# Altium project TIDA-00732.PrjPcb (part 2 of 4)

## Sheet TIDA-00732_ADC.SchDoc: Analog Front End & ADC
size 431 x 279 mm; Date: Not shown in title block; ApprovedBy: Not shown in title block; CheckedBy: Not shown in title block; Author: Not shown in title block; CompanyName: Not shown in title block; DrawnBy: Anbu Mani; Engineer: Not shown in title block; Organization: Not shown in title block; Address1: Not shown in title block; Address2: Not shown in title block; Address3: Not shown in title block; Address4: Not shown in title block; DocumentNumber: 1; Revision: Use project parameter SCH_Rev; SheetNumber: 4; SheetTotal: 10; PageSetup: Record=PageOptions¦CenterHorizontal=True¦CenterVertical=True¦PrintScale=1.00¦XCorrection=1.00¦YCorrection=1.00¦PrintKind=0¦BorderSize=5000000¦LeftOffset=0¦BottomOffset=0¦Orientation=2¦PaperLength=1000¦PaperWidth=1000¦Scale=100¦PaperSource=15¦PrintQuality=600¦MediaType=1¦DitherType=10¦PaperKind=Letter¦PrintScaleMode=1
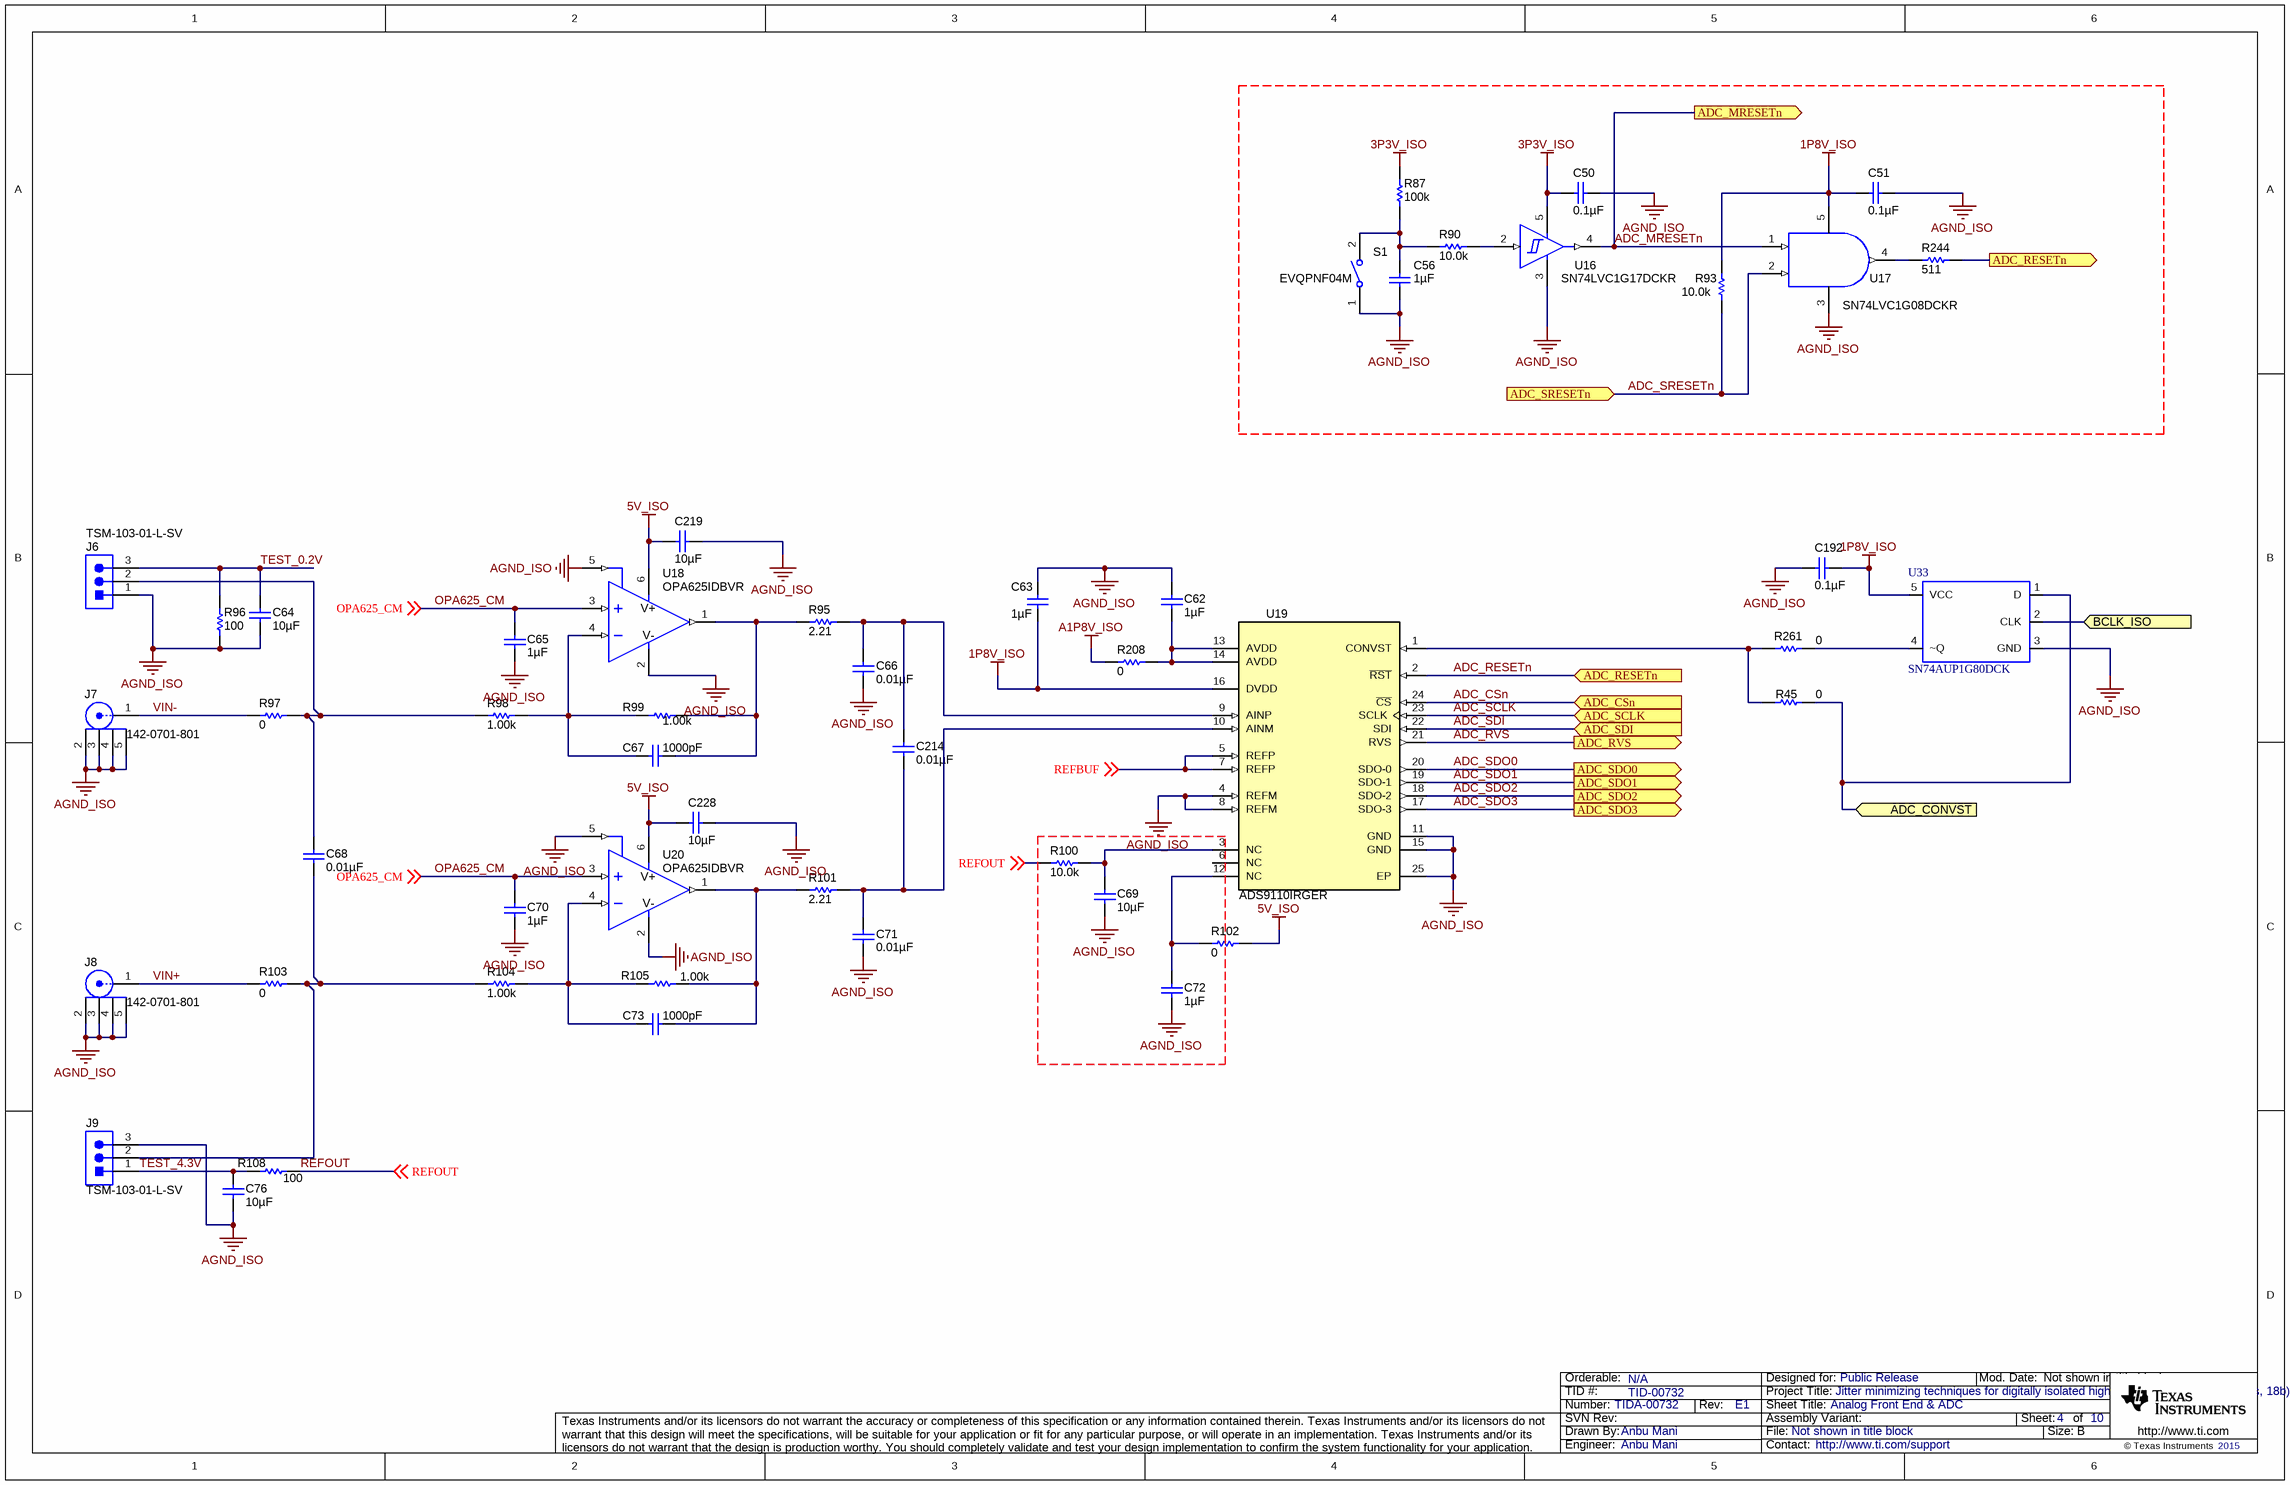
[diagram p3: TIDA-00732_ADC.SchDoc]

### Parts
C50  ValueDisplayed: 0.1µF  [0603]  (hidden comment: 0603YC104JAT2A)
C51  ValueDisplayed: 0.1µF  [0402]  (hidden comment: GRM155R71C104KA88D)
C56  ValueDisplayed: 1µF  [0603]  (hidden comment: GRM188R71E105KA12D)
C62  ValueDisplayed: 1µF  [0603]  (hidden comment: GRM188R71E105KA12D)
C63  ValueDisplayed: 1µF  [0603]  (hidden comment: GRM188R71E105KA12D)
C64  ValueDisplayed: 10µF  [0805_HV]  (hidden comment: GRM21BR71A106KE51L)
C65  ValueDisplayed: 1µF  [0603]  (hidden comment: GRM188R71E105KA12D)
C66  ValueDisplayed: 0.01µF  [0402]  (hidden comment: GRM155R71H103KA88D)
C67  ValueDisplayed: 1000pF  [0603]  (hidden comment: GRM1885C1H102FA01J)
C68  ValueDisplayed: 0.01µF  [0805_HV]  (hidden comment: C0805C103F1GACTU)
C69  ValueDisplayed: 10µF  [0805_HV]  (hidden comment: GRM21BR71A106KE51L)
C70  ValueDisplayed: 1µF  [0603]  (hidden comment: GRM188R71E105KA12D)
C71  ValueDisplayed: 0.01µF  [0402]  (hidden comment: GRM155R71H103KA88D)
C72  ValueDisplayed: 1µF  [0603]  (hidden comment: GRM188R71E105KA12D)
C73  ValueDisplayed: 1000pF  [0603]  (hidden comment: GRM1885C1H102FA01J)
C76  ValueDisplayed: 10µF  [0805_HV]  (hidden comment: GRM21BR71A106KE51L)
C192  ValueDisplayed: 0.1µF  [0402]  (hidden comment: GRM155R71C104KA88D)
C214  ValueDisplayed: 0.01µF  [0402]  (hidden comment: GRM155R71H103KA88D)
C219  ValueDisplayed: 10µF  [0603_120]  (hidden comment: ZRB18AD71A106KE01L)
C228  ValueDisplayed: 10µF  [0603_120]  (hidden comment: ZRB18AD71A106KE01L)
J6  TSM-103-01-L-SV  [Samtec_TSM-103-01-X-SV]
J7  142-0701-801  [JOHNSON_142-0701-801]
J8  142-0701-801  [JOHNSON_142-0701-801]
J9  TSM-103-01-L-SV  [Samtec_TSM-103-01-X-SV]
R45  ValueDisplayed: 0  [0402]  (hidden comment: CRCW04020000Z0ED)
R87  ValueDisplayed: 100k  [0402]  (hidden comment: CRCW0402100KFKED)
R90  ValueDisplayed: 10.0k  [0402]  (hidden comment: ERJ-2RKF1002X)
R93  ValueDisplayed: 10.0k  [0402]  (hidden comment: ERJ-2RKF1002X)
R95  ValueDisplayed: 2.21  [0603]  (hidden comment: CRCW06032R21FKEA)
R96  ValueDisplayed: 100  [0603]  (hidden comment: RG1608P-101-B-T5)
R97  ValueDisplayed: 0  [0603]  (hidden comment: ERJ-3GEY0R00V)
R98  ValueDisplayed: 1.00k  [0603]  (hidden comment: RG1608P-102-B-T5)
R99  ValueDisplayed: 1.00k  [0603]  (hidden comment: RG1608P-102-B-T5)
R100  ValueDisplayed: 10.0k  [0402]  (hidden comment: ERJ-2RKF1002X)
R101  ValueDisplayed: 2.21  [0603]  (hidden comment: CRCW06032R21FKEA)
R102  ValueDisplayed: 0  [0402]  (hidden comment: ERJ-2GE0R00X)
R103  ValueDisplayed: 0  [0603]  (hidden comment: ERJ-3GEY0R00V)
R104  ValueDisplayed: 1.00k  [0603]  (hidden comment: RG1608P-102-B-T5)
R105  ValueDisplayed: 1.00k  [0603]  (hidden comment: RG1608P-102-B-T5)
R108  ValueDisplayed: 100  [0603]  (hidden comment: RG1608P-101-B-T5)
R208  ValueDisplayed: 0  [0402]  (hidden comment: ERJ-2GE0R00X)
R244  ValueDisplayed: 511  [0603]  (hidden comment: RC0603FR-07511RL)
R261  ValueDisplayed: 0  [0402]  (hidden comment: CRCW04020000Z0ED)
S1  EVQPNF04M  [SW_EVQPNF04M]
U16  SN74LVC1G17DCKR  [DCK0005A_N]
U17  SN74LVC1G08DCKR  [DCK0005A_N]
U18  OPA625IDBVR  [DBV0006A_N]
U19  ADS9110IRGER  [RGE0024H]
U20  OPA625IDBVR  [DBV0006A_N]
U33  SN74AUP1G80DCK  [DCK-5]

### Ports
ADC_CONVST (in), ADC_CSn (in), ADC_MRESETn (out), ADC_RESETn (in), ADC_RESETn (out), ADC_RVS (out), ADC_SCLK (in), ADC_SDI (in), ADC_SDO0 (out), ADC_SDO1 (out), ADC_SDO2 (out), ADC_SDO3 (out), ADC_SRESETn (in), BCLK_ISO (in)

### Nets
1P8V_ISO: C51.2 C63.2 C192.2 R93.2 U17.5(V+) U19.16(DVDD) U33.5(VCC)
3P3V_ISO: C50.2 R87.2 U16.5(VCC)
5V_ISO: C219.2 C228.2 R102.2 U18.6(V+) U20.6(V+)
A1P8V_ISO: R208.1
AGND_ISO: C50.1 C51.1 C56.2 C62.2 C63.1 C64.2 C65.2 C66.2 C69.2 C70.2 C71.2 C72.2 C76.2 C192.1 C219.1 C228.1 J6.1 J7.2 J7.3 J7.4 J7.5 J8.2 J8.3 J8.4 J8.5 J9.3 R96.1 S1.1 U16.3(GND) U17.3(V-) U18.2(V-) U18.5(MODE) U19.4(REFM) U19.8(REFM) U19.11(GND) U19.15(GND) U19.25(EP) U20.2(V-) U20.5(MODE) U33.3(GND)
ADC_CONVST: R45.2 U33.1(D) ; port ADC_CONVST
ADC_CSn: U19.24(~{CS}) ; port ADC_CSn
ADC_MRESETn: U16.4(Y) U17.1(A) ; port ADC_MRESETn
ADC_RESETn: R244.2 U19.2(~{RST}) ; port ADC_RESETn
ADC_RVS: U19.21(RVS) ; port ADC_RVS
ADC_SCLK: U19.23(SCLK) ; port ADC_SCLK
ADC_SDI: U19.22(SDI) ; port ADC_SDI
ADC_SDO0: U19.20(SDO-0) ; port ADC_SDO0
ADC_SDO1: U19.19(SDO-1) ; port ADC_SDO1
ADC_SDO2: U19.18(SDO-2) ; port ADC_SDO2
ADC_SDO3: U19.17(SDO-3) ; port ADC_SDO3
ADC_SRESETn: R93.1 U17.2(B) ; port ADC_SRESETn
BCLK_ISO: U33.2(CLK) ; port BCLK_ISO
OPA625_CM: C65.1 C70.1 U18.3(IN+) U20.3(IN+) ; off-sheet OPA625_CM
REFBUF: U19.5(REFP) U19.7(REFP) ; off-sheet REFBUF
REFOUT: R100.1 R108.2 ; off-sheet REFOUT
TEST_0.2V: C64.1 J6.3 R96.2
TEST_4.3V: C76.1 J9.1 R108.1
VIN+: J8.1 R103.1
VIN-: J7.1 R97.1
NetC56_1: C56.1 R87.1 R90.1 S1.2
NetC62_1: C62.1 R208.2 U19.13(AVDD) U19.14(AVDD)
NetC66_1: C66.1 C214.1 R95.2 U19.9(AINP)
NetC67_1: C67.1 R95.1 R99.2 U18.1(OUT)
NetC67_2: C67.2 R98.2 R99.1 U18.4(IN-)
NetC68_1: C68.1 J9.2 R103.2 R104.1
NetC68_2: C68.2 J6.2 R97.2 R98.1
NetC69_1: C69.1 R100.2 U19.3(NC)
NetC71_1: C71.1 C214.2 R101.2 U19.10(AINM)
NetC72_1: C72.1 R102.1 U19.12(NC)
NetC73_1: C73.1 R101.1 R105.2 U20.1(OUT)
NetC73_2: C73.2 R104.2 R105.1 U20.4(IN-)
NetR45_1: R45.1 R261.1 U19.1(CONVST)
NetR90_2: R90.2 U16.2(A)
NetR244_1: R244.1 U17.4(Y)
NetR261_2: R261.2 U33.4(~Q)

Not connected (* = marked no-connect by the designer): U19 6(NC)

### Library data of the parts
C50 = 0603YC104JAT2A: CAP, CERM, 0.1 µF, 16 V, +/- 5%, X7R, 0603; Manufacturer: AVX; Polarized: N; CompType: Capacitor; Value: 0.1uF; U/M: EA; Cap_F: 0.0000001; Tolerance_%: 5; ESR_ohm: 0.039; Value1: 0.039 ohm; VDC_V: 16; Value2: 16V; TaMin_C: -55; TaMax_C: 125
C51 C192 = GRM155R71C104KA88D: CAP, CERM, 0.1 µF, 16 V, +/- 10%, X7R, 0402; Manufacturer: MuRata; Polarized: N; CompType: Capacitor; Value: 0.1uF; U/M: EA; Cap_F: 0.0000001; Tolerance_%: 10; Value1: Unknown; VDC_V: 16; Value2: 16V; TaMin_C: -55; TaMax_C: 125
C56 C62 C63 C65 C70 = GRM188R71E105KA12D: CAP, CERM, 1 µF, 25 V, +/- 10%, X7R, 0603; Manufacturer: MuRata; Polarized: N; CompType: Capacitor; Value: 1uF; U/M: EA; Cap_F: 0.000001; Tolerance_%: 10; Value1: Unknown; VDC_V: 25; Value2: 25V; TaMin_C: -55; TaMax_C: 125
C64 C69 C76 = GRM21BR71A106KE51L: CAP, CERM, 10 µF, 10 V, +/- 10%, X7R, 0805; Manufacturer: MuRata; Polarized: N; CompType: Capacitor; Value: 10uF; U/M: EA; Cap_F: 0.00001; Tolerance_%: 10; ESR_ohm: 0.003; Value1: 0.003 ohm; Value2: 10V; TaMin_C: -55; TaMax_C: 125; Cap_Case: 0805; AEC Category: Q200
C66 C71 C214 = GRM155R71H103KA88D: CAP, CERM, 0.01 µF, 50 V, +/- 10%, X7R, 0402; Manufacturer: MuRata; Polarized: N; CompType: Capacitor; Value: 0.01uF; U/M: EA; Cap_F: 0.00000001; Tolerance_%: 10; Value1: Unknown; VDC_V: 50; Value2: 50V; TaMin_C: -55; TaMax_C: 125
C67 C73 = GRM1885C1H102FA01J: CAP, CERM, 1000 pF, 50 V, +/- 1%, C0G/NP0, 0603; Manufacturer: MuRata; Polarized: N; CompType: Capacitor; Value: 1000pF; U/M: EA; Cap_F: 0.000000001; Tolerance_%: 1; Value1: Unknown; VDC_V: 50; Value2: 50V; TaMin_C: -55; TaMax_C: 125
C68 = C0805C103F1GACTU: CAP, CERM, 0.01 µF, 100 V, +/- 1%, C0G/NP0, 0805; Manufacturer: Kemet; Polarized: N; CompType: Capacitor; Value: 0.01uF; U/M: EA; Cap_F: 0.00000001; Tolerance_%: 1; Value1: Unknown; VDC_V: 100; Value2: 100V; TaMin_C: -55; TaMax_C: 125; Cap_Case: 0805; AEC Category: Q200
C72 = GRM188R71E105KA12D: CAP, CERM, 1 µF, 25 V, +/- 10%, X7R, 0603; Manufacturer: MuRata; Polarized: N; CompType: Capacitor; Value: 1uF; U/M: EA; Cap_F: 0.000001; Tolerance_%: 10; Value1: Unknown; VDC_V: 25; Value2: 25V; TaMin_C: -55; TaMax_C: 125; AEC Category: Q200
C219 C228 = ZRB18AD71A106KE01L: CAP, CERM, 10 µF, 10 V, +/- 10%, X7T, 0603; Manufacturer: MuRata; Polarized: N; CompType: Capacitor; Value: 10uF; U/M: EA; Cap_F: 0.00001; Tolerance_%: 10; Value1: Unknown; Value2: 10V; TaMin_C: -55; TaMax_C: 125; Cap_Case: 0603; AEC Category: Q200
J6 J9 = TSM-103-01-L-SV: Header, 100mil, 3x1, Gold, SMT; Manufacturer: Samtec; SymbolCreator: a0799628; U/M: EA
J7 J8 = 142-0701-801: Connector, End launch SMA, 50 ohm, SMT; Manufacturer: Johnson; SymbolCreator: X0208326; U/M: EA
R45 R261 = CRCW04020000Z0ED: RES, 0, 5%, 0.063 W, 0402; Manufacturer: Vishay-Dale; CompType: Resistor; Value: 0; Value_Code: 0000; Tolerance_%: 5; Power_W: 0.063; Value2: 0.063W; VDC_V: 50; TempCo: 200 ppm/C; EIA_Code: E24; U/M: EA; AEC Category: Q200
R87 = CRCW0402100KFKED: RES, 100 k, 1%, 0.063 W, 0402; Manufacturer: Vishay-Dale; CompType: Resistor; Value: 100k; Res_ohm: 100000; Tolerance_%: 1; Power_W: 0.063; Value2: 0.063W; VDC_V: 50; TempCo: 100 ppm/C; EIA_Code: E96; U/M: EA
R90 R93 = ERJ-2RKF1002X: RES, 10.0 k, 1%, 0.1 W, 0402; Manufacturer: Panasonic; CompType: Resistor; Value: 10.0k; Res_ohm: 10000; Value_Code: 10k0; Tolerance_%: 1; Power_W: 0.1; Value2: 0.1W; VDC_V: 50; TempCo: 100 ppm/C; EIA_Code: E96; U/M: EA
R95 R101 = CRCW06032R21FKEA: RES, 2.21, 1%, 0.1 W, 0603; Manufacturer: Vishay-Dale; CompType: Resistor; Value: 2.21; Value_Code: 2R21; Tolerance_%: 1; Power_W: 0.1; Value2: 0.1W; VDC_V: 75; TempCo: 100 ppm/C; EIA_Code: E96; U/M: EA
R96 R108 = RG1608P-101-B-T5: RES, 100, 0.1%, 0.1 W, 0603; Manufacturer: Susumu Co Ltd; CompType: Resistor; Value: 100; Value_Code: 100R; Tolerance_%: 0.1; Value2: 0.1W; VDC_V: 75; TempCo: 25 ppm/C; EIA_Code: E192; U/M: EA; AEC Category: Q200
R97 R103 = ERJ-3GEY0R00V: RES, 0, 5%, 0.1 W, 0603; Manufacturer: Panasonic; CompType: Resistor; Value: 0; Value_Code: 0000; Tolerance_%: 5; Power_W: 0.1; Value2: 0.1W; VDC_V: 50; TempCo: 600 ppm/C; EIA_Code: E24; U/M: EA; AEC Category: Q200
R98 R99 R104 R105 = RG1608P-102-B-T5: RES, 1.00 k, 0.1%, 0.1 W, 0603; Manufacturer: Susumu Co Ltd; CompType: Resistor; Value: 1.00k; Res_ohm: 1000; Value_Code: 1k00; Tolerance_%: 0.1; Value2: 0.1W; VDC_V: 75; TempCo: 25 ppm/C; EIA_Code: E192; U/M: EA
R100 = ERJ-2RKF1002X: RES, 10.0 k, 1%, 0.1 W, 0402; Manufacturer: Panasonic; CompType: Resistor; Value: 10.0k; Res_ohm: 10000; Value_Code: 10k0; Tolerance_%: 1; Power_W: 0.1; Value2: 0.1W; VDC_V: 50; TempCo: 100 ppm/C; EIA_Code: E96; U/M: EA; AEC Category: Q200
R102 R208 = ERJ-2GE0R00X: RES, 0, 5%, 0.063 W, 0402; Manufacturer: Panasonic; CompType: Resistor; Value: 0; Value_Code: 0000; Tolerance_%: 5; Power_W: 0.063; Value2: 0.063W; VDC_V: 50; TempCo: 600 ppm/C; EIA_Code: E24; U/M: EA; AEC Category: Q200
R244 = RC0603FR-07511RL: RES, 511, 1%, 0.1 W, 0603; Manufacturer: Yageo America; CompType: Resistor; Value: 511; Value_Code: 511R; Tolerance_%: 1; Power_W: 0.1; Value2: 0.1W; VDC_V: 150; TempCo: 200 ppm/C; EIA_Code: E96; U/M: EA; AEC Category: Q200
S1 = EVQPNF04M: Switch, Tactile, SPST-NO, 0.05A, 12V, SMD; Manufacturer: Panasonic; SymbolCreator: a0799628; Circuit: SPST; VDC_V: 12; SwitchFunction: Off-Mom; PositionCount: 1; CurrentRating_mA: 50
U16 = SN74LVC1G17DCKR: SINGLE SCHMITT-TRIGGER BUFFER, DCK0005A; Alternate PartNumber: SN74LVC1G17DCKT; Manufacturer: Texas Instruments; SymbolCreator: a0799628; CompType: IC; U/M: EA
U17 = SN74LVC1G08DCKR: Single 2-Input Positive-AND Gate, DCK0005A; Alternate PartNumber: SN74LVC1G08DCKT; Manufacturer: Texas Instruments; CompType: IC; U/M: EA
U18 U20 = OPA625IDBVR: High-Bandwidth, High-Precision, Low THD+N, 16-Bit and 18-Bit Analog-to-Digital Converter (ADC) Drivers, DBV0006A; Alternate PartNumber: OPA625IDBVT; Manufacturer: Texas Instruments; SymbolCreator: Altium; CompType: IC; U/M: EA
U19 = ADS9110IRGER: 18-Bit, 2-MSPS, 20-mW, SAR ADC with Enhanced Serial Interface, RGE0024H; Alternate PartNumber: ADS9110IRGET; Manufacturer: Texas Instruments; SymbolCreator: Altium; CompType: IC; U/M: EA
U33 = SN74AUP1G80DCK: IC, Single Positive-Edge-Triggered D-Type Flip-Flop; Manufacturer: TI; Alternate Manufacturer: None; Area: 23200

## Sheet TIDA-00732_FPGA_1.SchDoc: FPGA 1 - Isolated End
size 431 x 279 mm; Date: Not shown in title block; ApprovedBy: Not shown in title block; CheckedBy: Not shown in title block; Author: Not shown in title block; CompanyName: Not shown in title block; DrawnBy: Anbu Mani; Engineer: Not shown in title block; Organization: Not shown in title block; Address1: Not shown in title block; Address2: Not shown in title block; Address3: Not shown in title block; Address4: Not shown in title block; DocumentNumber: 1; Revision: Use project parameter SCH_Rev; SheetNumber: 5; SheetTotal: 10; PageSetup: Record=PageOptions¦CenterHorizontal=True¦CenterVertical=True¦PrintScale=1.00¦XCorrection=1.00¦YCorrection=1.00¦PrintKind=0¦BorderSize=5000000¦LeftOffset=0¦BottomOffset=0¦Orientation=2¦PaperLength=1000¦PaperWidth=1000¦Scale=100¦PaperSource=15¦PrintQuality=600¦MediaType=1¦DitherType=10¦PaperKind=Letter¦PrintScaleMode=1
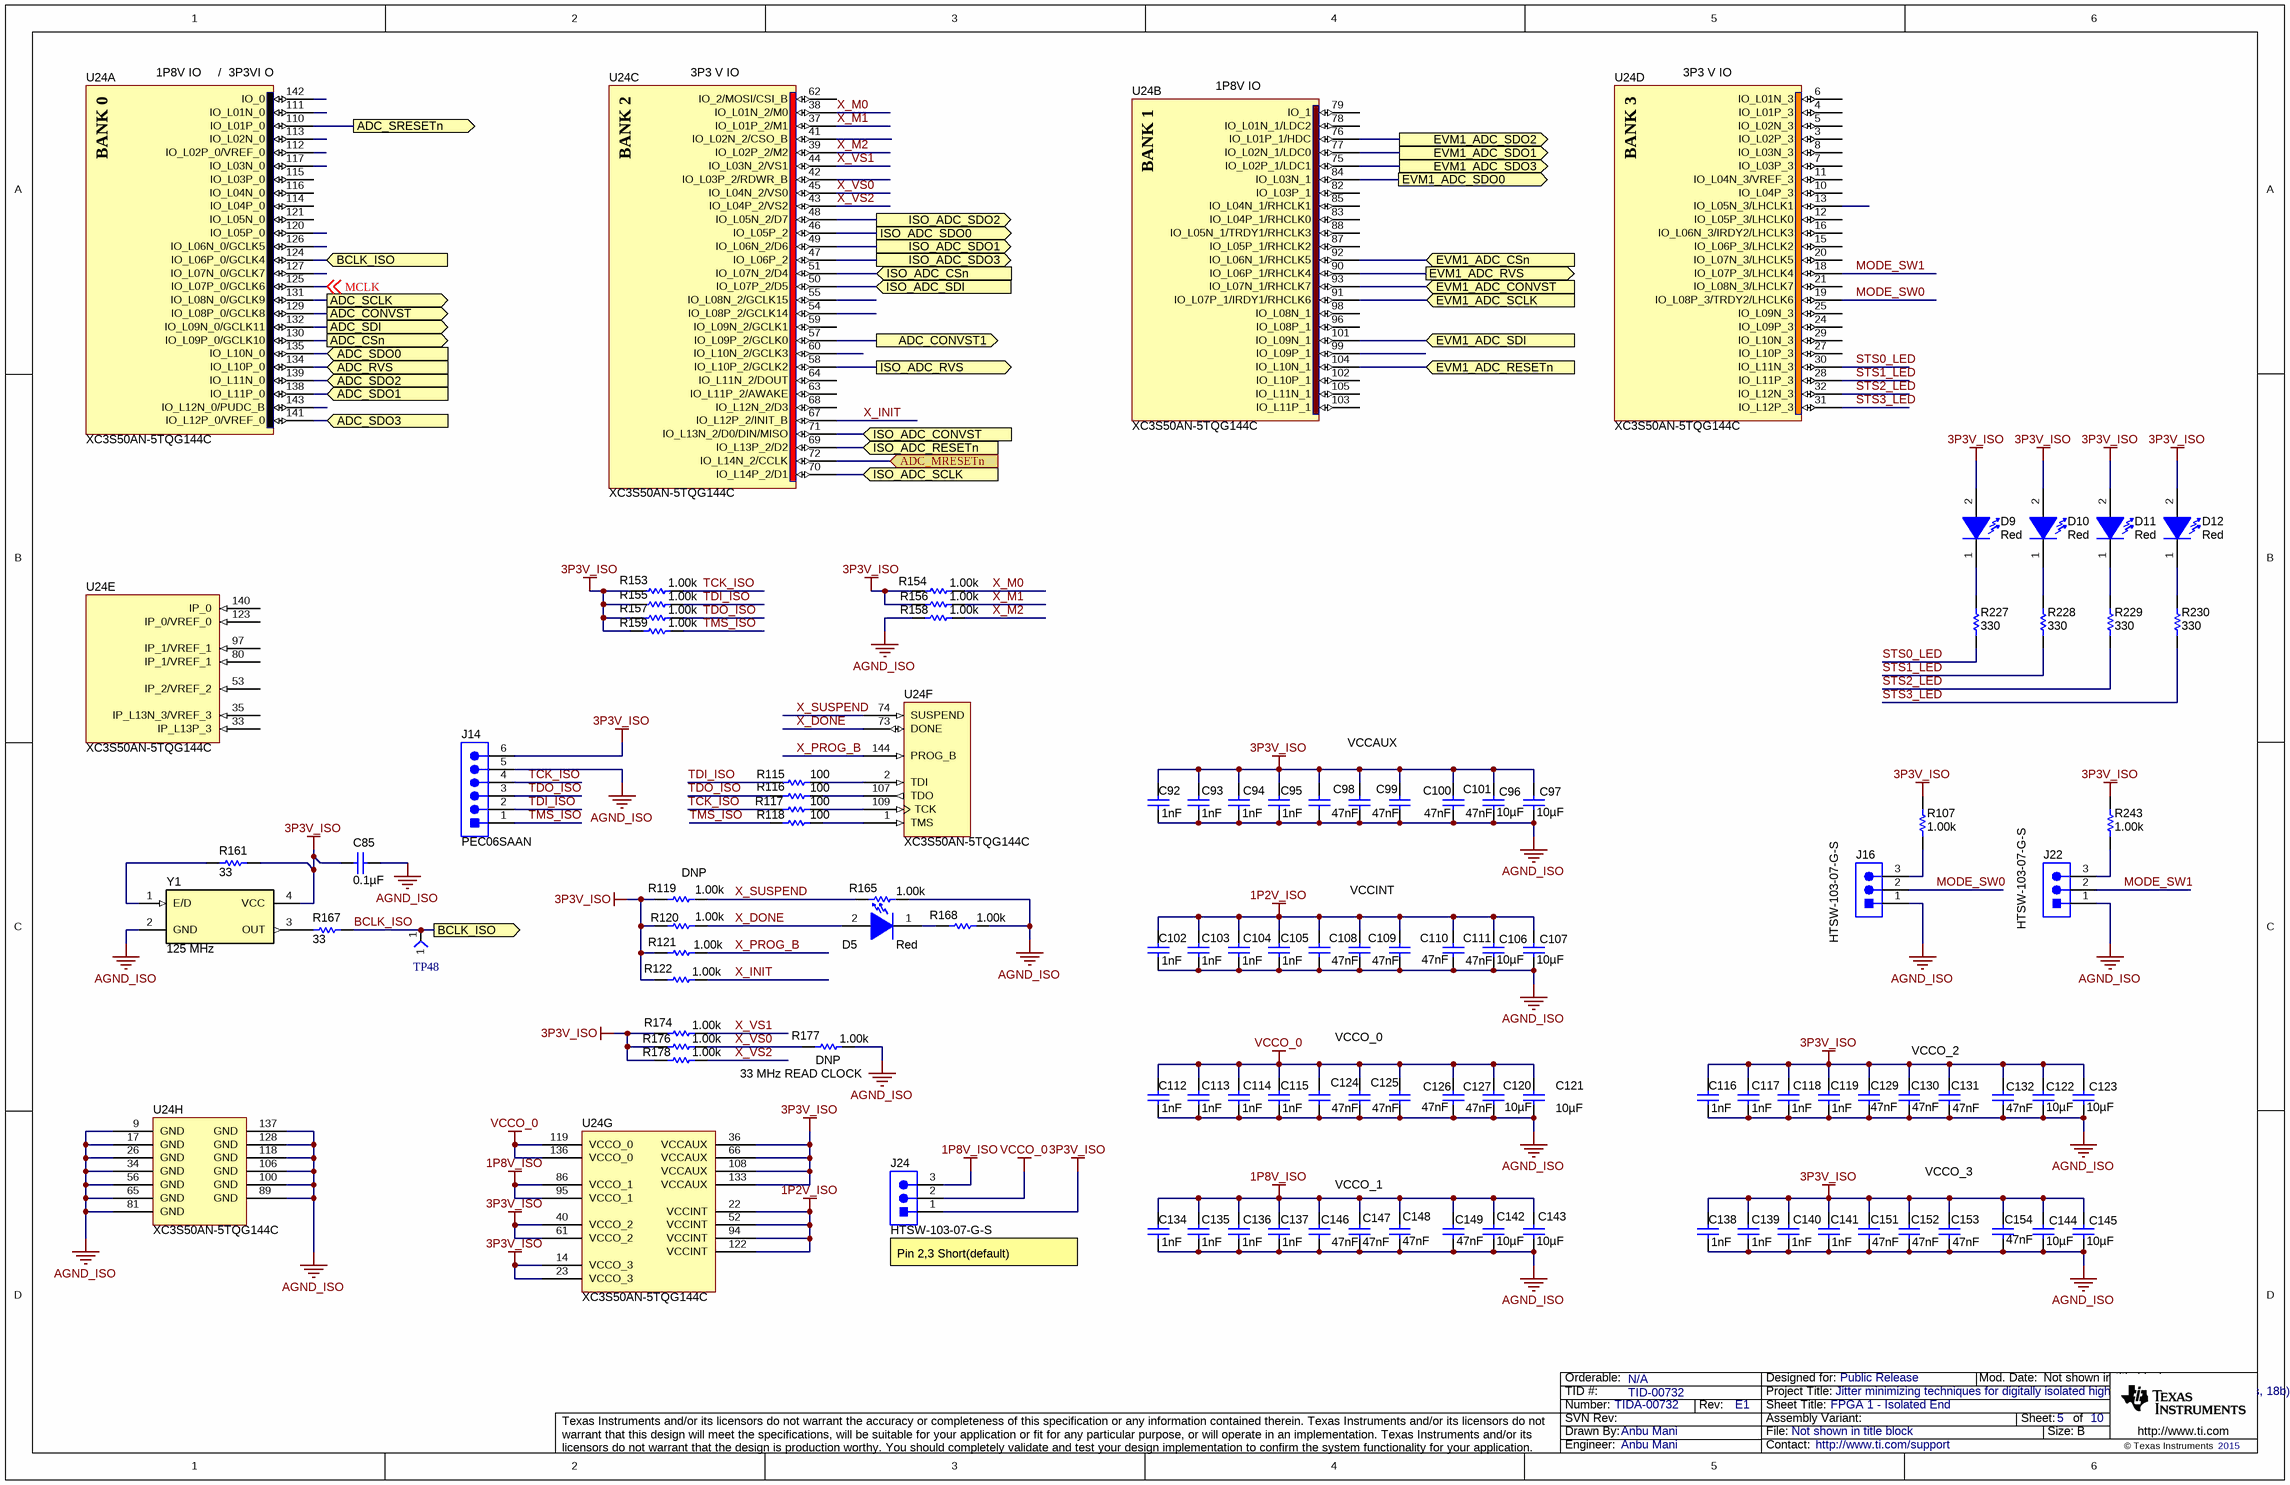
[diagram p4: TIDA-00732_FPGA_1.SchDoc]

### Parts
C85  ValueDisplayed: 0.1µF  [0402]  (hidden comment: GRM155R71C104KA88D)
C92  ValueDisplayed: 1nF  [0402]  (hidden comment: C1005X7R1H102M)
C93  ValueDisplayed: 1nF  [0402]  (hidden comment: C1005X7R1H102M)
C94  ValueDisplayed: 1nF  [0402]  (hidden comment: C1005X7R1H102M)
C95  ValueDisplayed: 1nF  [0402]  (hidden comment: C1005X7R1H102M)
C96  ValueDisplayed: 10µF  [0603_120]  (hidden comment: ZRB18AD71A106KE01L)
C97  ValueDisplayed: 10µF  [0603_120]  (hidden comment: ZRB18AD71A106KE01L)
C98  ValueDisplayed: 47nF  [0402]  (hidden comment: GRM155R61A473KA01D)
C99  ValueDisplayed: 47nF  [0402]  (hidden comment: GRM155R61A473KA01D)
C100  ValueDisplayed: 47nF  [0402]  (hidden comment: GRM155R61A473KA01D)
C101  ValueDisplayed: 47nF  [0402]  (hidden comment: GRM155R61A473KA01D)
C102  ValueDisplayed: 1nF  [0402]  (hidden comment: C1005X7R1H102M)
C103  ValueDisplayed: 1nF  [0402]  (hidden comment: C1005X7R1H102M)
C104  ValueDisplayed: 1nF  [0402]  (hidden comment: C1005X7R1H102M)
C105  ValueDisplayed: 1nF  [0402]  (hidden comment: C1005X7R1H102M)
C106  ValueDisplayed: 10µF  [0603_120]  (hidden comment: ZRB18AD71A106KE01L)
C107  ValueDisplayed: 10µF  [0603_120]  (hidden comment: ZRB18AD71A106KE01L)
C108  ValueDisplayed: 47nF  [0402]  (hidden comment: GRM155R61A473KA01D)
C109  ValueDisplayed: 47nF  [0402]  (hidden comment: GRM155R61A473KA01D)
C110  ValueDisplayed: 47nF  [0402]  (hidden comment: GRM155R61A473KA01D)
C111  ValueDisplayed: 47nF  [0402]  (hidden comment: GRM155R61A473KA01D)
C112  ValueDisplayed: 1nF  [0402]  (hidden comment: C1005X7R1H102M)
C113  ValueDisplayed: 1nF  [0402]  (hidden comment: C1005X7R1H102M)
C114  ValueDisplayed: 1nF  [0402]  (hidden comment: C1005X7R1H102M)
C115  ValueDisplayed: 1nF  [0402]  (hidden comment: C1005X7R1H102M)
C116  ValueDisplayed: 1nF  [0402]  (hidden comment: C1005X7R1H102M)
C117  ValueDisplayed: 1nF  [0402]  (hidden comment: C1005X7R1H102M)
C118  ValueDisplayed: 1nF  [0402]  (hidden comment: C1005X7R1H102M)
C119  ValueDisplayed: 1nF  [0402]  (hidden comment: C1005X7R1H102M)
C120  ValueDisplayed: 10µF  [0603_120]  (hidden comment: ZRB18AD71A106KE01L)
C121  ValueDisplayed: 10µF  [0603_120]  (hidden comment: ZRB18AD71A106KE01L)
C122  ValueDisplayed: 10µF  [0603_120]  (hidden comment: ZRB18AD71A106KE01L)
C123  ValueDisplayed: 10µF  [0603_120]  (hidden comment: ZRB18AD71A106KE01L)
C124  ValueDisplayed: 47nF  [0402]  (hidden comment: GRM155R61A473KA01D)
C125  ValueDisplayed: 47nF  [0402]  (hidden comment: GRM155R61A473KA01D)
C126  ValueDisplayed: 47nF  [0402]  (hidden comment: GRM155R61A473KA01D)
C127  ValueDisplayed: 47nF  [0402]  (hidden comment: GRM155R61A473KA01D)
C129  ValueDisplayed: 47nF  [0402]  (hidden comment: GRM155R61A473KA01D)
C130  ValueDisplayed: 47nF  [0402]  (hidden comment: GRM155R61A473KA01D)
C131  ValueDisplayed: 47nF  [0402]  (hidden comment: GRM155R61A473KA01D)
C132  ValueDisplayed: 47nF  [0402]  (hidden comment: GRM155R61A473KA01D)
C134  ValueDisplayed: 1nF  [0402]  (hidden comment: C1005X7R1H102M)
C135  ValueDisplayed: 1nF  [0402]  (hidden comment: C1005X7R1H102M)
C136  ValueDisplayed: 1nF  [0402]  (hidden comment: C1005X7R1H102M)
C137  ValueDisplayed: 1nF  [0402]  (hidden comment: C1005X7R1H102M)
C138  ValueDisplayed: 1nF  [0402]  (hidden comment: C1005X7R1H102M)
C139  ValueDisplayed: 1nF  [0402]  (hidden comment: C1005X7R1H102M)
C140  ValueDisplayed: 1nF  [0402]  (hidden comment: C1005X7R1H102M)
C141  ValueDisplayed: 1nF  [0402]  (hidden comment: C1005X7R1H102M)
C142  ValueDisplayed: 10µF  [0603_120]  (hidden comment: ZRB18AD71A106KE01L)
C143  ValueDisplayed: 10µF  [0603_120]  (hidden comment: ZRB18AD71A106KE01L)
C144  ValueDisplayed: 10µF  [0603_120]  (hidden comment: ZRB18AD71A106KE01L)
C145  ValueDisplayed: 10µF  [0603_120]  (hidden comment: ZRB18AD71A106KE01L)
C146  ValueDisplayed: 47nF  [0402]  (hidden comment: GRM155R61A473KA01D)
C147  ValueDisplayed: 47nF  [0402]  (hidden comment: GRM155R61A473KA01D)
C148  ValueDisplayed: 47nF  [0402]  (hidden comment: GRM155R61A473KA01D)
C149  ValueDisplayed: 47nF  [0402]  (hidden comment: GRM155R61A473KA01D)
C151  ValueDisplayed: 47nF  [0402]  (hidden comment: GRM155R61A473KA01D)
C152  ValueDisplayed: 47nF  [0402]  (hidden comment: GRM155R61A473KA01D)
C153  ValueDisplayed: 47nF  [0402]  (hidden comment: GRM155R61A473KA01D)
C154  ValueDisplayed: 47nF  [0402]  (hidden comment: GRM155R61A473KA01D)
D5  value Red  [WL-SMCW_RED]  (hidden comment: 150060RS75000)
D9  value Red  [WL-SMCW_RED]  (hidden comment: 150060RS75000)
D10  value Red  [WL-SMCW_RED]  (hidden comment: 150060RS75000)
D11  value Red  [WL-SMCW_RED]  (hidden comment: 150060RS75000)
D12  value Red  [WL-SMCW_RED]  (hidden comment: 150060RS75000)
J14  PEC06SAAN  [Sullins_PEC06SAAN]
J16  HTSW-103-07-G-S  [Samtec_HTSW-103-07-G-S]
J22  HTSW-103-07-G-S  [Samtec_HTSW-103-07-G-S]
J24  HTSW-103-07-G-S  [Samtec_HTSW-103-07-G-S]
R107  ValueDisplayed: 1.00k  [0603]  (hidden comment: RC0603FR-071KL)
R115  ValueDisplayed: 100  [0603]  (hidden comment: RG1608P-101-B-T5)
R116  ValueDisplayed: 100  [0603]  (hidden comment: RG1608P-101-B-T5)
R117  ValueDisplayed: 100  [0603]  (hidden comment: RG1608P-101-B-T5)
R118  ValueDisplayed: 100  [0603]  (hidden comment: RG1608P-101-B-T5)
R119  ValueDisplayed: 1.00k  [0603]  (hidden comment: RC0603FR-071KL)
R120  ValueDisplayed: 1.00k  [0603]  (hidden comment: RC0603FR-071KL)
R121  ValueDisplayed: 1.00k  [0603]  (hidden comment: RC0603FR-071KL)
R122  ValueDisplayed: 1.00k  [0603]  (hidden comment: RC0603FR-071KL)
R153  ValueDisplayed: 1.00k  [0603]  (hidden comment: RC0603FR-071KL)
R154  ValueDisplayed: 1.00k  [0603]  (hidden comment: RC0603FR-071KL)
R155  ValueDisplayed: 1.00k  [0603]  (hidden comment: RC0603FR-071KL)
R156  ValueDisplayed: 1.00k  [0603]  (hidden comment: RC0603FR-071KL)
R157  ValueDisplayed: 1.00k  [0603]  (hidden comment: RC0603FR-071KL)
R158  ValueDisplayed: 1.00k  [0603]  (hidden comment: RC0603FR-071KL)
R159  ValueDisplayed: 1.00k  [0603]  (hidden comment: RC0603FR-071KL)
R161  ValueDisplayed: 33  [0402]  (hidden comment: CRCW040233R0JNED)
R165  ValueDisplayed: 1.00k  [0603]  (hidden comment: RC0603FR-071KL)
R167  ValueDisplayed: 33  [0402]  (hidden comment: CRCW040233R0JNED)
R168  ValueDisplayed: 1.00k  [0603]  (hidden comment: RC0603FR-071KL)
R174  ValueDisplayed: 1.00k  [0603]  (hidden comment: RC0603FR-071KL)
R176  ValueDisplayed: 1.00k  [0603]  (hidden comment: RC0603FR-071KL)
R177  ValueDisplayed: 1.00k  [0603]  (hidden comment: RC0603FR-071KL)
R178  ValueDisplayed: 1.00k  [0603]  (hidden comment: RC0603FR-071KL)
R227  ValueDisplayed: 330  [0603]  (hidden comment: RC0603JR-07330RL)
R228  ValueDisplayed: 330  [0603]  (hidden comment: RC0603JR-07330RL)
R229  ValueDisplayed: 330  [0603]  (hidden comment: RC0603JR-07330RL)
R230  ValueDisplayed: 330  [0603]  (hidden comment: RC0603JR-07330RL)
R243  ValueDisplayed: 1.00k  [0603]  (hidden comment: RC0603FR-071KL)
TP48  TP-025-SMT  [TP_25MIL-SMT]  (value not drawn)
U24  XC3S50AN-5TQG144C  [TQ144_N]  (parts A,B,C,D,E,F,G,H of 8)
Y1  Frequency: 125 MHz  [TXC_AU]  (hidden comment: ASTMLPE-125.000MHZ-LJ-E-T)

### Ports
ADC_CONVST1 (out), ADC_CONVST (out), ADC_CSn (out), ADC_MRESETn (in), ADC_RVS (in), ADC_SCLK (out), ADC_SDI (out), ADC_SDO0 (in), ADC_SDO1 (in), ADC_SDO2 (in), ADC_SDO3 (in), ADC_SRESETn (out), BCLK_ISO (in), BCLK_ISO (out), EVM1_ADC_CONVST (in), EVM1_ADC_CSn (in), EVM1_ADC_RESETn (in), EVM1_ADC_RVS (out), EVM1_ADC_SCLK (in), EVM1_ADC_SDI (in), EVM1_ADC_SDO0 (out), EVM1_ADC_SDO1 (out), EVM1_ADC_SDO2 (out), EVM1_ADC_SDO3 (out), ISO_ADC_CONVST (in), ISO_ADC_CSn (in), ISO_ADC_RESETn (in), ISO_ADC_RVS (out), ISO_ADC_SCLK (in), ISO_ADC_SDI (in), ISO_ADC_SDO0 (out), ISO_ADC_SDO1 (out), ISO_ADC_SDO2 (out), ISO_ADC_SDO3 (out)

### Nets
1P2V_ISO: C102.1 C103.1 C104.1 C105.1 C106.1 C107.1 C108.1 C109.1 C110.1 C111.1 U24.22(VCCINT) U24.52(VCCINT) U24.94(VCCINT) U24.122(VCCINT)
1P8V_ISO: C134.1 C135.1 C136.1 C137.1 C142.1 C143.1 C146.1 C147.1 C148.1 C149.1 J24.3 U24.86(VCCO_1) U24.95(VCCO_1)
3P3V_ISO: C85.1 C92.1 C93.1 C94.1 C95.1 C96.1 C97.1 C98.1 C99.1 C100.1 C101.1 C116.1 C117.1 C118.1 C119.1 C122.1 C123.1 C129.1 C130.1 C131.1 C132.1 C138.1 C139.1 C140.1 C141.1 C144.1 C145.1 C151.1 C152.1 C153.1 C154.1 D9.2(A) D10.2(A) D11.2(A) D12.2(A) J14.6 J24.1 R107.2 R119.2 R120.1 R121.1 R122.1 R153.1 R154.1 R155.1 R156.1 R157.1 R159.1 R161.2 R174.1 R176.1 R178.1 R243.2 U24.14(VCCO_3) U24.23(VCCO_3) U24.36(VCCAUX) U24.40(VCCO_2) U24.61(VCCO_2) U24.66(VCCAUX) U24.108(VCCAUX) U24.133(VCCAUX) Y1.4(VCC)
AGND_ISO: C85.2 C92.2 C93.2 C94.2 C95.2 C96.2 C97.2 C98.2 C99.2 C100.2 C101.2 C102.2 C103.2 C104.2 C105.2 C106.2 C107.2 C108.2 C109.2 C110.2 C111.2 C112.2 C113.2 C114.2 C115.2 C116.2 C117.2 C118.2 C119.2 C120.2 C121.2 C122.2 C123.2 C124.2 C125.2 C126.2 C127.2 C129.2 C130.2 C131.2 C132.2 C134.2 C135.2 C136.2 C137.2 C138.2 C139.2 C140.2 C141.2 C142.2 C143.2 C144.2 C145.2 C146.2 C147.2 C148.2 C149.2 C151.2 C152.2 C153.2 C154.2 J14.5 J16.1 J22.1 R158.1 R165.1 R168.1 R177.2 U24.9(GND) U24.17(GND) U24.26(GND) U24.34(GND) U24.56(GND) U24.65(GND) U24.81(GND) U24.89(GND) U24.100(GND) U24.106(GND) U24.118(GND) U24.128(GND) U24.137(GND) Y1.2(GND)
VCCO_0: C112.1 C113.1 C114.1 C115.1 C120.1 C121.1 C124.1 C125.1 C126.1 C127.1 J24.2 U24.119(VCCO_0) U24.136(VCCO_0)
ADC_CONVST: U24.129(IO_L08P_0/GCLK8) ; port ADC_CONVST
ADC_CONVST1: U24.57(IO_L09P_2/GCLK0) ; port ADC_CONVST1
ADC_CSn: U24.130(IO_L09P_0/GCLK10) ; port ADC_CSn
ADC_MRESETn: U24.72(IO_L14N_2/CCLK) ; port ADC_MRESETn
ADC_RVS: U24.134(IO_L10P_0) ; port ADC_RVS
ADC_SCLK: U24.131(IO_L08N_0/GCLK9) ; port ADC_SCLK
ADC_SDI: U24.132(IO_L09N_0/GCLK11) ; port ADC_SDI
ADC_SDO0: U24.135(IO_L10N_0) ; port ADC_SDO0
ADC_SDO1: U24.138(IO_L11P_0) ; port ADC_SDO1
ADC_SDO2: U24.139(IO_L11N_0) ; port ADC_SDO2
ADC_SDO3: U24.141(IO_L12P_0/VREF_0) ; port ADC_SDO3
ADC_SRESETn: U24.110(IO_L01P_0) ; port ADC_SRESETn
BCLK_ISO: R167.2 TP48.1 U24.124(IO_L06P_0/GCLK4) ; port BCLK_ISO
EVM1_ADC_CONVST: U24.93(IO_L07N_1/RHCLK7) ; port EVM1_ADC_CONVST
EVM1_ADC_CSn: U24.92(IO_L06N_1/RHCLK5) ; port EVM1_ADC_CSn
EVM1_ADC_RESETn: U24.104(IO_L10N_1) ; port EVM1_ADC_RESETn
EVM1_ADC_RVS: U24.90(IO_L06P_1/RHCLK4) ; port EVM1_ADC_RVS
EVM1_ADC_SCLK: U24.91(IO_L07P_1/IRDY1/RHCLK6) ; port EVM1_ADC_SCLK
EVM1_ADC_SDI: U24.101(IO_L09N_1) ; port EVM1_ADC_SDI
EVM1_ADC_SDO0: U24.84(IO_L03N_1) ; port EVM1_ADC_SDO0
EVM1_ADC_SDO1: U24.77(IO_L02N_1/LDC0) ; port EVM1_ADC_SDO1
EVM1_ADC_SDO2: U24.76(IO_L01P_1/HDC) ; port EVM1_ADC_SDO2
EVM1_ADC_SDO3: U24.75(IO_L02P_1/LDC1) ; port EVM1_ADC_SDO3
ISO_ADC_CONVST: U24.71(IO_L13N_2/D0/DIN/MISO) ; port ISO_ADC_CONVST
ISO_ADC_CSn: U24.51(IO_L07N_2/D4) ; port ISO_ADC_CSn
ISO_ADC_RESETn: U24.69(IO_L13P_2/D2) ; port ISO_ADC_RESETn
ISO_ADC_RVS: U24.58(IO_L10P_2/GCLK2) ; port ISO_ADC_RVS
ISO_ADC_SCLK: U24.70(IO_L14P_2/D1) ; port ISO_ADC_SCLK
ISO_ADC_SDI: U24.50(IO_L07P_2/D5) ; port ISO_ADC_SDI
ISO_ADC_SDO0: U24.46(IO_L05P_2) ; port ISO_ADC_SDO0
ISO_ADC_SDO1: U24.49(IO_L06N_2/D6) ; port ISO_ADC_SDO1
ISO_ADC_SDO2: U24.48(IO_L05N_2/D7) ; port ISO_ADC_SDO2
ISO_ADC_SDO3: U24.47(IO_L06P_2) ; port ISO_ADC_SDO3
MCLK: U24.125(IO_L07P_0/GCLK6) ; off-sheet MCLK
MODE_SW0: J16.2 U24.19(IO_L08P_3/TRDY2/LHCLK6)
MODE_SW1: J22.2 U24.18(IO_L07P_3/LHCLK4)
STS0_LED: R227.1 U24.30(IO_L11N_3)
STS1_LED: R228.1 U24.28(IO_L11P_3)
STS2_LED: R229.1 U24.32(IO_L12N_3)
STS3_LED: R230.1 U24.31(IO_L12P_3)
TCK_ISO: J14.4 R117.1 R153.2
TDI_ISO: J14.2 R115.1 R155.2
TDO_ISO: J14.3 R116.1 R157.2
TMS_ISO: J14.1 R118.1 R159.2
X_DONE: D5.2(A) R120.2 U24.73(DONE)
X_INIT: R122.2 U24.67(IO_L12P_2/INIT_B)
X_M0: R154.2 U24.38(IO_L01N_2/M0)
X_M1: R156.2 U24.37(IO_L01P_2/M1)
X_M2: R158.2 U24.39(IO_L02P_2/M2)
X_PROG_B: R121.2 U24.144(PROG_B)
X_SUSPEND: R119.1 R165.2 U24.74(SUSPEND)
X_VS0: R176.2 R177.1 U24.45(IO_L04N_2/VS0)
X_VS1: R174.2 U24.44(IO_L03N_2/VS1)
X_VS2: R178.2 U24.43(IO_L04P_2/VS2)
NetD5_1: D5.1(K) R168.2
NetD9_1: D9.1(K) R227.2
NetD10_1: D10.1(K) R228.2
NetD11_1: D11.1(K) R229.2
NetD12_1: D12.1(K) R230.2
NetJ16_3: J16.3 R107.1
NetJ22_3: J22.3 R243.1
NetR115_2: R115.2 U24.2(TDI)
NetR116_2: R116.2 U24.107(TDO)
NetR117_2: R117.2 U24.109(TCK)
NetR118_2: R118.2 U24.1(TMS)
NetR161_1: R161.1 Y1.1(E/D)
NetR167_1: R167.1 Y1.3(OUT)

Not connected (* = marked no-connect by the designer): U24 3(IO_L02P_3) 4(IO_L01P_3) 5(IO_L02N_3) 6(IO_L01N_3) 7(IO_L03P_3) 8(IO_L03N_3) 10(IO_L04P_3) 11(IO_L04N_3/VREF_3) 12(IO_L05P_3/LHCLK0) 13(IO_L05N_3/LHCLK1) 15(IO_L06P_3/LHCLK2) 16(IO_L06N_3/IRDY2/LHCLK3) 20(IO_L07N_3/LHCLK5) 21(IO_L08N_3/LHCLK7) 24(IO_L09P_3) 25(IO_L09N_3) 27(IO_L10P_3) 29(IO_L10N_3) 33(IP_L13P_3) 35(IP_L13N_3/VREF_3) 41(IO_L02N_2/CSO_B) 42(IO_L03P_2/RDWR_B) 53(IP_2/VREF_2) 54(IO_L08P_2/GCLK14) 55(IO_L08N_2/GCLK15) 59(IO_L09N_2/GCLK1) 60(IO_L10N_2/GCLK3) 62(IO_2/MOSI/CSI_B) 63(IO_L11P_2/AWAKE) 64(IO_L11N_2/DOUT) 68(IO_L12N_2/D3) 78(IO_L01N_1/LDC2) 79(IO_1) 80(IP_1/VREF_1) 82(IO_L03P_1) 83(IO_L04P_1/RHCLK0) 85(IO_L04N_1/RHCLK1) 87(IO_L05P_1/RHCLK2) 88(IO_L05N_1/TRDY1/RHCLK3) 96(IO_L08P_1) 97(IP_1/VREF_1) 98(IO_L08N_1) 99(IO_L09P_1) 102(IO_L10P_1) 103(IO_L11P_1) 105(IO_L11N_1) 111(IO_L01N_0) 112(IO_L02P_0/VREF_0) 113(IO_L02N_0) 114(IO_L04P_0) 115(IO_L03P_0) 116(IO_L04N_0) 117(IO_L03N_0) 120(IO_L05P_0) 121(IO_L05N_0) 123(IP_0/VREF_0) 126(IO_L06N_0/GCLK5) 127(IO_L07N_0/GCLK7) 140(IP_0) 142(IO_0) 143(IO_L12N_0/PUDC_B)

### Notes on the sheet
- 1P8V IO
- (near U24) /  3P3VI O
- 3P3 V IO
- VCCAUX
- (near R119) DNP
- VCCINT
- VCCO_0
- (near R177) 33 MHz READ CLOCK
- (near R177) DNP
- VCCO_2
- VCCO_3
- VCCO_1
- (near J24) Pin 2,3 Short(default)

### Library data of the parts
C85 = GRM155R71C104KA88D: as C51 on sheet TIDA-00732_ADC
C92-C95 C102-C105 C112-C119 C134-C141 = C1005X7R1H102M: CAP, CERM, 1000 pF, 50 V, +/- 20%, X7R, 0402; Manufacturer: TDK; Polarized: N; CompType: Capacitor; Value: 1000pF; U/M: EA; Cap_F: 0.000000001; Tolerance_%: 20; ESR_ohm: 0.005; Value1: 0.005 ohm; VDC_V: 50; Value2: 50V; TaMin_C: -55; TaMax_C: 125; AEC Category: Q200
C96 C97 C106 C107 C120-C123 C142-C145 = ZRB18AD71A106KE01L: as C219 on sheet TIDA-00732_ADC
C98-C101 C108-C111 C124-C127 C129-C132 C146-C149 C151-C154 = GRM155R61A473KA01D: CAP, CERM, 0.047 µF, 10 V, +/- 10%, X5R, 0402; Manufacturer: MuRata; Polarized: N; CompType: Capacitor; Value: 0.047uF; U/M: EA; Cap_F: 0.000000047; Tolerance_%: 10; Value1: Unknown; Value2: 10V; TaMin_C: -55; TaMax_C: 85; AEC Category: Q200
D5 D9-D12 = 150060RS75000: LED, Red, SMD; Manufacturer: Wurth Elektronik; Type: AlInGaP; Vf_V: 2; Value2: 2V; Io_A: 0.03; Vr_V: 5; Tjmax_C: 85; Power_TotalModule: 0.072; Value1: 0.072W; Angle: 140; U/M: EA
J14 = PEC06SAAN: Header, 100mil, 6x1, Tin, TH; Manufacturer: Sullins Connector Solutions; SymbolCreator: a0412235; U/M: EA
J16 J22 J24 = HTSW-103-07-G-S: Header, 100mil, 3x1, Gold, TH; Manufacturer: Samtec; SymbolCreator: a0799628; U/M: EA
R107 R119-R122 R153-R159 R165 R168 R174 R176-R178 R243 = RC0603FR-071KL: RES, 1.00 k, 1%, 0.1 W, 0603; Manufacturer: Yageo America; CompType: Resistor; Value: 1.00k; Res_ohm: 1000; Value_Code: 1k00; Tolerance_%: 1; Power_W: 0.1; Value2: 0.1W; VDC_V: 150; TempCo: 200 ppm/C; EIA_Code: E96; U/M: EA; AEC Category: Q200
R115-R118 = RG1608P-101-B-T5: as R96 on sheet TIDA-00732_ADC
R161 R167 = CRCW040233R0JNED: RES, 33, 5%, 0.063 W, 0402; Manufacturer: Vishay-Dale; CompType: Resistor; Value: 33; Value_Code: 33R0; Tolerance_%: 5; Power_W: 0.063; Value2: 0.063W; VDC_V: 50; TempCo: 200 ppm/C; EIA_Code: E24; U/M: EA; AEC Category: Q200
R227-R230 = RC0603JR-07330RL: RES, 330, 5%, 0.1 W, 0603; Manufacturer: Yageo America; CompType: Resistor; Value: 330; Value_Code: 330R; Tolerance_%: 5; Power_W: 0.1; Value2: 0.1W; VDC_V: 50; TempCo: 100 ppm/C; EIA_Code: E24; U/M: EA; AEC Category: Q200
TP48 = TP-025-SMT: Test Point, O.025"; Manufacturer: STD; Value: STD
U24 = XC3S50AN-4TQ144C: Spartan-3AN Non-Volatile FPGA, 108 User I/Os, 144-Pin TQFP, Standard Performance, Commercial Grade
Y1 = AU-40.000MDE-T: OSC, 125 MHz, 3.3V, SMD; Manufacturer: ABRACON; SymbolCreator: a0411947; CompType: Oscillator; U/M: EA; TaMin_C: -40; TaMax_C: 85; Frequency Stability: ±50ppm

## Sheet TIDA-00732_FPGA_2.SchDoc: FPGA 2- Non-Isolated End
size 431 x 279 mm; Date: Not shown in title block; ApprovedBy: Not shown in title block; CheckedBy: Not shown in title block; Author: Not shown in title block; CompanyName: Not shown in title block; DrawnBy: Anbu Mani; Engineer: Not shown in title block; Organization: Not shown in title block; Address1: Not shown in title block; Address2: Not shown in title block; Address3: Not shown in title block; Address4: Not shown in title block; DocumentNumber: 1; Revision: Use project parameter SCH_Rev; SheetNumber: 6; SheetTotal: 10; PageSetup: Record=PageOptions¦CenterHorizontal=True¦CenterVertical=True¦PrintScale=1.00¦XCorrection=1.00¦YCorrection=1.00¦PrintKind=0¦BorderSize=5000000¦LeftOffset=0¦BottomOffset=0¦Orientation=2¦PaperLength=1000¦PaperWidth=1000¦Scale=100¦PaperSource=15¦PrintQuality=600¦MediaType=1¦DitherType=10¦PaperKind=Letter¦PrintScaleMode=1
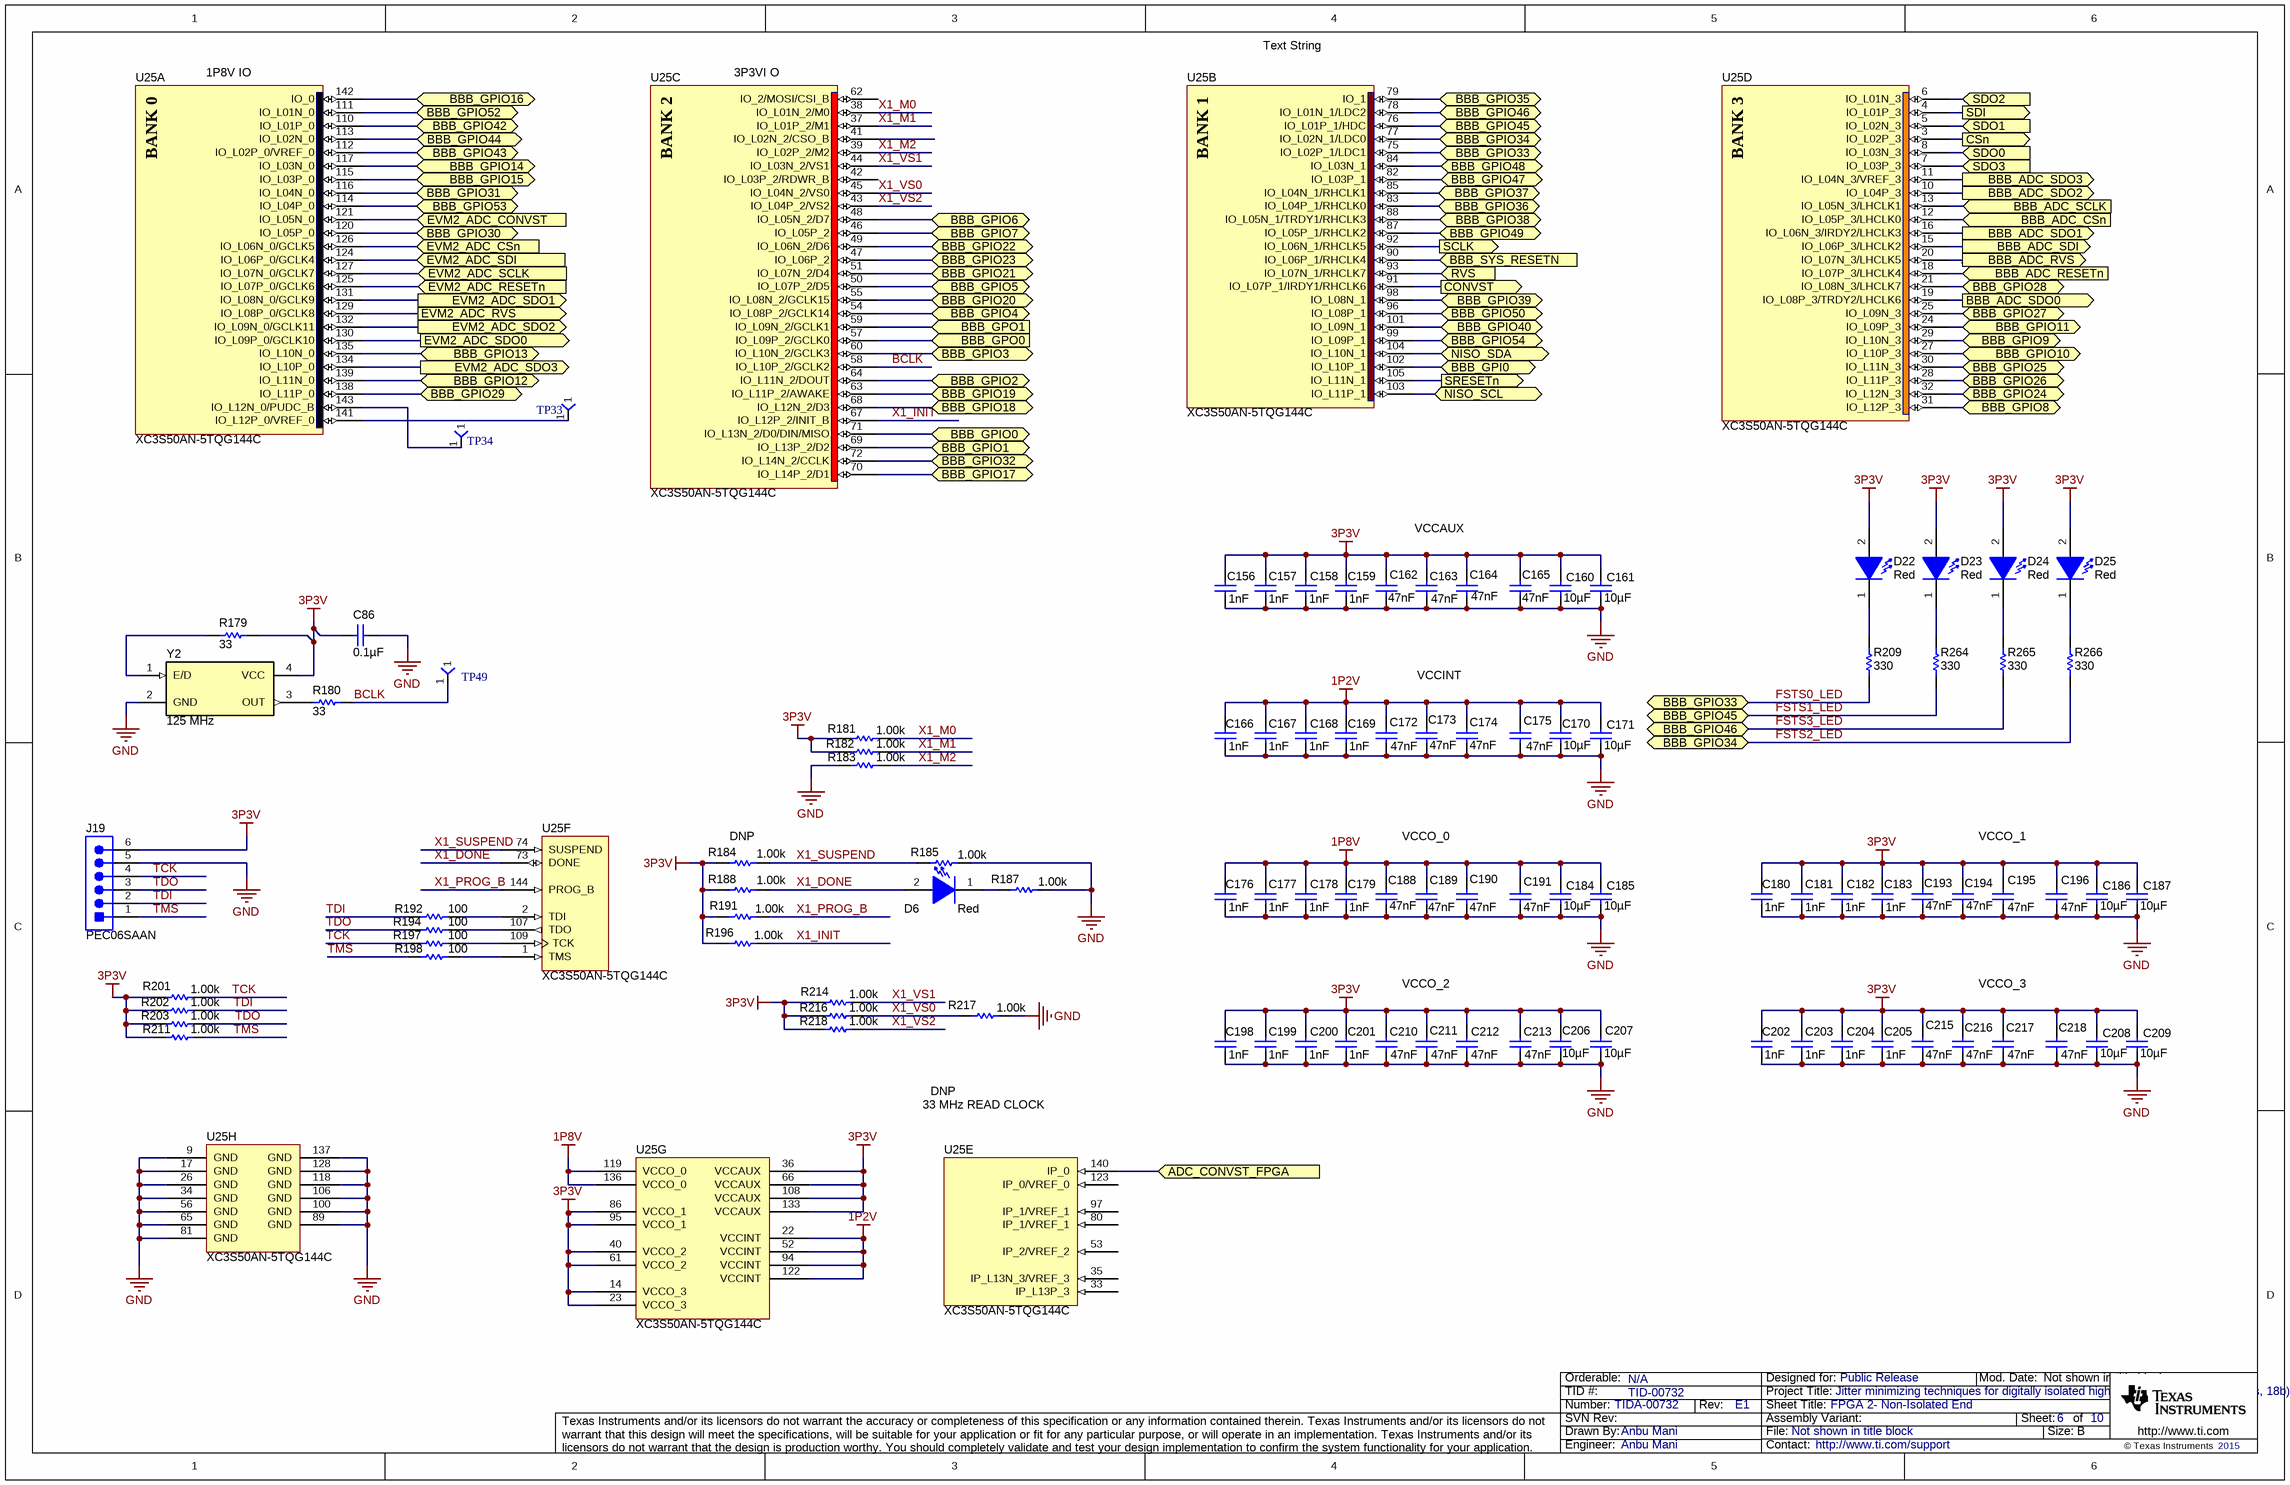
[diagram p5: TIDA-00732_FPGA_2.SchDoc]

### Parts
C86  ValueDisplayed: 0.1µF  [0402]  (hidden comment: GRM155R71C104KA88D)
C156  ValueDisplayed: 1nF  [0402]  (hidden comment: C1005X7R1H102M)
C157  ValueDisplayed: 1nF  [0402]  (hidden comment: C1005X7R1H102M)
C158  ValueDisplayed: 1nF  [0402]  (hidden comment: C1005X7R1H102M)
C159  ValueDisplayed: 1nF  [0402]  (hidden comment: C1005X7R1H102M)
C160  ValueDisplayed: 10µF  [0603_120]  (hidden comment: ZRB18AD71A106KE01L)
C161  ValueDisplayed: 10µF  [0603_120]  (hidden comment: ZRB18AD71A106KE01L)
C162  ValueDisplayed: 47nF  [0402]  (hidden comment: GRM155R61A473KA01D)
C163  ValueDisplayed: 47nF  [0402]  (hidden comment: GRM155R61A473KA01D)
C164  ValueDisplayed: 47nF  [0402]  (hidden comment: GRM155R61A473KA01D)
C165  ValueDisplayed: 47nF  [0402]  (hidden comment: GRM155R61A473KA01D)
C166  ValueDisplayed: 1nF  [0402]  (hidden comment: C1005X7R1H102M)
C167  ValueDisplayed: 1nF  [0402]  (hidden comment: C1005X7R1H102M)
C168  ValueDisplayed: 1nF  [0402]  (hidden comment: C1005X7R1H102M)
C169  ValueDisplayed: 1nF  [0402]  (hidden comment: C1005X7R1H102M)
C170  ValueDisplayed: 10µF  [0603_120]  (hidden comment: ZRB18AD71A106KE01L)
C171  ValueDisplayed: 10µF  [0603_120]  (hidden comment: ZRB18AD71A106KE01L)
C172  ValueDisplayed: 47nF  [0402]  (hidden comment: GRM155R61A473KA01D)
C173  ValueDisplayed: 47nF  [0402]  (hidden comment: GRM155R61A473KA01D)
C174  ValueDisplayed: 47nF  [0402]  (hidden comment: GRM155R61A473KA01D)
C175  ValueDisplayed: 47nF  [0402]  (hidden comment: GRM155R61A473KA01D)
C176  ValueDisplayed: 1nF  [0402]  (hidden comment: C1005X7R1H102M)
C177  ValueDisplayed: 1nF  [0402]  (hidden comment: C1005X7R1H102M)
C178  ValueDisplayed: 1nF  [0402]  (hidden comment: C1005X7R1H102M)
C179  ValueDisplayed: 1nF  [0402]  (hidden comment: C1005X7R1H102M)
C180  ValueDisplayed: 1nF  [0402]  (hidden comment: C1005X7R1H102M)
C181  ValueDisplayed: 1nF  [0402]  (hidden comment: C1005X7R1H102M)
C182  ValueDisplayed: 1nF  [0402]  (hidden comment: C1005X7R1H102M)
C183  ValueDisplayed: 1nF  [0402]  (hidden comment: C1005X7R1H102M)
C184  ValueDisplayed: 10µF  [0603_120]  (hidden comment: ZRB18AD71A106KE01L)
C185  ValueDisplayed: 10µF  [0603_120]  (hidden comment: ZRB18AD71A106KE01L)
C186  ValueDisplayed: 10µF  [0603_120]  (hidden comment: ZRB18AD71A106KE01L)
C187  ValueDisplayed: 10µF  [0603_120]  (hidden comment: ZRB18AD71A106KE01L)
C188  ValueDisplayed: 47nF  [0402]  (hidden comment: GRM155R61A473KA01D)
C189  ValueDisplayed: 47nF  [0402]  (hidden comment: GRM155R61A473KA01D)
C190  ValueDisplayed: 47nF  [0402]  (hidden comment: GRM155R61A473KA01D)
C191  ValueDisplayed: 47nF  [0402]  (hidden comment: GRM155R61A473KA01D)
C193  ValueDisplayed: 47nF  [0402]  (hidden comment: GRM155R61A473KA01D)
C194  ValueDisplayed: 47nF  [0402]  (hidden comment: GRM155R61A473KA01D)
C195  ValueDisplayed: 47nF  [0402]  (hidden comment: GRM155R61A473KA01D)
C196  ValueDisplayed: 47nF  [0402]  (hidden comment: GRM155R61A473KA01D)
C198  ValueDisplayed: 1nF  [0402]  (hidden comment: C1005X7R1H102M)
C199  ValueDisplayed: 1nF  [0402]  (hidden comment: C1005X7R1H102M)
C200  ValueDisplayed: 1nF  [0402]  (hidden comment: C1005X7R1H102M)
C201  ValueDisplayed: 1nF  [0402]  (hidden comment: C1005X7R1H102M)
C202  ValueDisplayed: 1nF  [0402]  (hidden comment: C1005X7R1H102M)
C203  ValueDisplayed: 1nF  [0402]  (hidden comment: C1005X7R1H102M)
C204  ValueDisplayed: 1nF  [0402]  (hidden comment: C1005X7R1H102M)
C205  ValueDisplayed: 1nF  [0402]  (hidden comment: C1005X7R1H102M)
C206  ValueDisplayed: 10µF  [0603_120]  (hidden comment: ZRB18AD71A106KE01L)
C207  ValueDisplayed: 10µF  [0603_120]  (hidden comment: ZRB18AD71A106KE01L)
C208  ValueDisplayed: 10µF  [0603_120]  (hidden comment: ZRB18AD71A106KE01L)
C209  ValueDisplayed: 10µF  [0603_120]  (hidden comment: ZRB18AD71A106KE01L)
C210  ValueDisplayed: 47nF  [0402]  (hidden comment: GRM155R61A473KA01D)
C211  ValueDisplayed: 47nF  [0402]  (hidden comment: GRM155R61A473KA01D)
C212  ValueDisplayed: 47nF  [0402]  (hidden comment: GRM155R61A473KA01D)
C213  ValueDisplayed: 47nF  [0402]  (hidden comment: GRM155R61A473KA01D)
C215  ValueDisplayed: 47nF  [0402]  (hidden comment: GRM155R61A473KA01D)
C216  ValueDisplayed: 47nF  [0402]  (hidden comment: GRM155R61A473KA01D)
C217  ValueDisplayed: 47nF  [0402]  (hidden comment: GRM155R61A473KA01D)
C218  ValueDisplayed: 47nF  [0402]  (hidden comment: GRM155R61A473KA01D)
D6  value Red  [WL-SMCW_RED]  (hidden comment: 150060RS75000)
D22  value Red  [WL-SMCW_RED]  (hidden comment: 150060RS75000)
D23  value Red  [WL-SMCW_RED]  (hidden comment: 150060RS75000)
D24  value Red  [WL-SMCW_RED]  (hidden comment: 150060RS75000)
D25  value Red  [WL-SMCW_RED]  (hidden comment: 150060RS75000)
J19  PEC06SAAN  [Sullins_PEC06SAAN]
R179  ValueDisplayed: 33  [0402]  (hidden comment: CRCW040233R0JNED)
R180  ValueDisplayed: 33  [0402]  (hidden comment: CRCW040233R0JNED)
R181  ValueDisplayed: 1.00k  [0603]  (hidden comment: RC0603FR-071KL)
R182  ValueDisplayed: 1.00k  [0603]  (hidden comment: RC0603FR-071KL)
R183  ValueDisplayed: 1.00k  [0603]  (hidden comment: RC0603FR-071KL)
R184  ValueDisplayed: 1.00k  [0603]  (hidden comment: RC0603FR-071KL)
R185  ValueDisplayed: 1.00k  [0603]  (hidden comment: RC0603FR-071KL)
R187  ValueDisplayed: 1.00k  [0603]  (hidden comment: RC0603FR-071KL)
R188  ValueDisplayed: 1.00k  [0603]  (hidden comment: RC0603FR-071KL)
R191  ValueDisplayed: 1.00k  [0603]  (hidden comment: RC0603FR-071KL)
R192  ValueDisplayed: 100  [0603]  (hidden comment: RG1608P-101-B-T5)
R194  ValueDisplayed: 100  [0603]  (hidden comment: RG1608P-101-B-T5)
R196  ValueDisplayed: 1.00k  [0603]  (hidden comment: RC0603FR-071KL)
R197  ValueDisplayed: 100  [0603]  (hidden comment: RG1608P-101-B-T5)
R198  ValueDisplayed: 100  [0603]  (hidden comment: RG1608P-101-B-T5)
R201  ValueDisplayed: 1.00k  [0603]  (hidden comment: RC0603FR-071KL)
R202  ValueDisplayed: 1.00k  [0603]  (hidden comment: RC0603FR-071KL)
R203  ValueDisplayed: 1.00k  [0603]  (hidden comment: RC0603FR-071KL)
R209  ValueDisplayed: 330  [0603]  (hidden comment: RC0603JR-07330RL)
R211  ValueDisplayed: 1.00k  [0603]  (hidden comment: RC0603FR-071KL)
R214  ValueDisplayed: 1.00k  [0603]  (hidden comment: RC0603FR-071KL)
R216  ValueDisplayed: 1.00k  [0603]  (hidden comment: RC0603FR-071KL)
R217  ValueDisplayed: 1.00k  [0603]  (hidden comment: RC0603FR-071KL)
R218  ValueDisplayed: 1.00k  [0603]  (hidden comment: RC0603FR-071KL)
R264  ValueDisplayed: 330  [0603]  (hidden comment: RC0603JR-07330RL)
R265  ValueDisplayed: 330  [0603]  (hidden comment: RC0603JR-07330RL)
R266  ValueDisplayed: 330  [0603]  (hidden comment: RC0603JR-07330RL)
TP33  TP-025-SMT  [TP_25MIL-SMT]  (value not drawn)
TP34  TP-025-SMT  [TP_25MIL-SMT]  (value not drawn)
TP49  TP-025-SMT  [TP_25MIL-SMT]  (value not drawn)
U25  XC3S50AN-5TQG144C  [TQ144_N]  (parts A,B,C,D,E,F,G,H of 8)
Y2  Frequency: 125 MHz  [TXC_AU]  (hidden comment: ASTMLPE-125.000MHZ-LJ-E-T)

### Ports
ADC_CONVST_FPGA (in), BBB_ADC_CSn (in), BBB_ADC_RESETn (in), BBB_ADC_RVS (out), BBB_ADC_SCLK (in), BBB_ADC_SDI (out), BBB_ADC_SDO0 (out), BBB_ADC_SDO1 (out), BBB_ADC_SDO2 (out), BBB_ADC_SDO3 (out), BBB_GPI0 (bidir), BBB_GPIO0 (bidir), BBB_GPIO1 (bidir), BBB_GPIO2 (bidir), BBB_GPIO3 (bidir), BBB_GPIO4 (bidir), BBB_GPIO5 (bidir), BBB_GPIO6 (bidir), BBB_GPIO7 (bidir), BBB_GPIO8 (bidir), BBB_GPIO9 (bidir), BBB_GPIO10 (bidir), BBB_GPIO11 (bidir), BBB_GPIO12 (bidir), BBB_GPIO13 (bidir), BBB_GPIO14 (bidir), BBB_GPIO15 (bidir), BBB_GPIO16 (bidir), BBB_GPIO17 (bidir), BBB_GPIO18 (bidir), BBB_GPIO19 (bidir), BBB_GPIO20 (bidir), BBB_GPIO21 (bidir), BBB_GPIO22 (bidir), BBB_GPIO23 (bidir), BBB_GPIO24 (bidir), BBB_GPIO25 (bidir), BBB_GPIO26 (bidir), BBB_GPIO27 (bidir), BBB_GPIO28 (bidir), BBB_GPIO29 (bidir), BBB_GPIO30 (bidir), BBB_GPIO31 (bidir), BBB_GPIO32 (bidir), BBB_GPIO33 (bidir), BBB_GPIO34 (bidir), BBB_GPIO35 (bidir), BBB_GPIO36 (bidir), BBB_GPIO37 (bidir), BBB_GPIO38 (bidir), BBB_GPIO39 (bidir), BBB_GPIO40 (bidir), BBB_GPIO42 (bidir), BBB_GPIO43 (bidir), BBB_GPIO44 (bidir), BBB_GPIO45 (bidir), BBB_GPIO46 (bidir), BBB_GPIO47 (bidir), BBB_GPIO48 (bidir), BBB_GPIO49 (bidir), BBB_GPIO50 (bidir), BBB_GPIO52 (bidir), BBB_GPIO53 (bidir), BBB_GPIO54 (bidir), BBB_GPO0 (in), BBB_GPO1 (in), BBB_SYS_RESETN (in), CONVST (out), CSn (out), EVM2_ADC_CONVST (in), EVM2_ADC_CSn (in), EVM2_ADC_RESETn (in), EVM2_ADC_RVS (out), EVM2_ADC_SCLK (in), EVM2_ADC_SDI (in), EVM2_ADC_SDO0 (out), EVM2_ADC_SDO1 (out), EVM2_ADC_SDO2 (out), EVM2_ADC_SDO3 (out), NISO_SCL (bidir), NISO_SDA (bidir), RVS (in), SCLK (out), SDI (out), SDO0 (in), SDO1 (in), SDO2 (in), SDO3 (in), SRESETn (out)

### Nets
1P2V: C166.1 C167.1 C168.1 C169.1 C170.1 C171.1 C172.1 C173.1 C174.1 C175.1 U25.22(VCCINT) U25.52(VCCINT) U25.94(VCCINT) U25.122(VCCINT)
1P8V: C176.1 C177.1 C178.1 C179.1 C184.1 C185.1 C188.1 C189.1 C190.1 C191.1 U25.119(VCCO_0) U25.136(VCCO_0)
3P3V: C86.1 C156.1 C157.1 C158.1 C159.1 C160.1 C161.1 C162.1 C163.1 C164.1 C165.1 C180.1 C181.1 C182.1 C183.1 C186.1 C187.1 C193.1 C194.1 C195.1 C196.1 C198.1 C199.1 C200.1 C201.1 C202.1 C203.1 C204.1 C205.1 C206.1 C207.1 C208.1 C209.1 C210.1 C211.1 C212.1 C213.1 C215.1 C216.1 C217.1 C218.1 D22.2(A) D23.2(A) D24.2(A) D25.2(A) J19.6 R179.2 R181.1 R182.1 R184.2 R188.1 R191.1 R196.1 R201.1 R202.1 R203.1 R211.1 R214.1 R216.1 R218.1 U25.14(VCCO_3) U25.23(VCCO_3) U25.36(VCCAUX) U25.40(VCCO_2) U25.61(VCCO_2) U25.66(VCCAUX) U25.86(VCCO_1) U25.95(VCCO_1) U25.108(VCCAUX) U25.133(VCCAUX) Y2.4(VCC)
GND: C86.2 C156.2 C157.2 C158.2 C159.2 C160.2 C161.2 C162.2 C163.2 C164.2 C165.2 C166.2 C167.2 C168.2 C169.2 C170.2 C171.2 C172.2 C173.2 C174.2 C175.2 C176.2 C177.2 C178.2 C179.2 C180.2 C181.2 C182.2 C183.2 C184.2 C185.2 C186.2 C187.2 C188.2 C189.2 C190.2 C191.2 C193.2 C194.2 C195.2 C196.2 C198.2 C199.2 C200.2 C201.2 C202.2 C203.2 C204.2 C205.2 C206.2 C207.2 C208.2 C209.2 C210.2 C211.2 C212.2 C213.2 C215.2 C216.2 C217.2 C218.2 J19.5 R183.1 R185.1 R187.1 R217.2 U25.9(GND) U25.17(GND) U25.26(GND) U25.34(GND) U25.56(GND) U25.65(GND) U25.81(GND) U25.89(GND) U25.100(GND) U25.106(GND) U25.118(GND) U25.128(GND) U25.137(GND) Y2.2(GND)
ADC_CONVST_FPGA: U25.140(IP_0) ; port ADC_CONVST_FPGA
BBB_ADC_CSn: U25.12(IO_L05P_3/LHCLK0) ; port BBB_ADC_CSn
BBB_ADC_RESETn: U25.18(IO_L07P_3/LHCLK4) ; port BBB_ADC_RESETn
BBB_ADC_RVS: U25.20(IO_L07N_3/LHCLK5) ; port BBB_ADC_RVS
BBB_ADC_SCLK: U25.13(IO_L05N_3/LHCLK1) ; port BBB_ADC_SCLK
BBB_ADC_SDI: U25.15(IO_L06P_3/LHCLK2) ; port BBB_ADC_SDI
BBB_ADC_SDO0: U25.19(IO_L08P_3/TRDY2/LHCLK6) ; port BBB_ADC_SDO0
BBB_ADC_SDO1: U25.16(IO_L06N_3/IRDY2/LHCLK3) ; port BBB_ADC_SDO1
BBB_ADC_SDO2: U25.10(IO_L04P_3) ; port BBB_ADC_SDO2
BBB_ADC_SDO3: U25.11(IO_L04N_3/VREF_3) ; port BBB_ADC_SDO3
BBB_GPI0: U25.102(IO_L10P_1) ; port BBB_GPI0
BBB_GPIO0: U25.71(IO_L13N_2/D0/DIN/MISO) ; port BBB_GPIO0
BBB_GPIO1: U25.69(IO_L13P_2/D2) ; port BBB_GPIO1
BBB_GPIO2: U25.64(IO_L11N_2/DOUT) ; port BBB_GPIO2
BBB_GPIO3: U25.60(IO_L10N_2/GCLK3) ; port BBB_GPIO3
BBB_GPIO4: U25.54(IO_L08P_2/GCLK14) ; port BBB_GPIO4
BBB_GPIO5: U25.50(IO_L07P_2/D5) ; port BBB_GPIO5
BBB_GPIO6: U25.48(IO_L05N_2/D7) ; port BBB_GPIO6
BBB_GPIO7: U25.46(IO_L05P_2) ; port BBB_GPIO7
BBB_GPIO8: U25.31(IO_L12P_3) ; port BBB_GPIO8
BBB_GPIO9: U25.29(IO_L10N_3) ; port BBB_GPIO9
BBB_GPIO10: U25.27(IO_L10P_3) ; port BBB_GPIO10
BBB_GPIO11: U25.24(IO_L09P_3) ; port BBB_GPIO11
BBB_GPIO12: U25.139(IO_L11N_0) ; port BBB_GPIO12
BBB_GPIO13: U25.135(IO_L10N_0) ; port BBB_GPIO13
BBB_GPIO14: U25.117(IO_L03N_0) ; port BBB_GPIO14
BBB_GPIO15: U25.115(IO_L03P_0) ; port BBB_GPIO15
BBB_GPIO16: U25.142(IO_0) ; port BBB_GPIO16
BBB_GPIO17: U25.70(IO_L14P_2/D1) ; port BBB_GPIO17
BBB_GPIO18: U25.68(IO_L12N_2/D3) ; port BBB_GPIO18
BBB_GPIO19: U25.63(IO_L11P_2/AWAKE) ; port BBB_GPIO19
BBB_GPIO20: U25.55(IO_L08N_2/GCLK15) ; port BBB_GPIO20
BBB_GPIO21: U25.51(IO_L07N_2/D4) ; port BBB_GPIO21
BBB_GPIO22: U25.49(IO_L06N_2/D6) ; port BBB_GPIO22
BBB_GPIO23: U25.47(IO_L06P_2) ; port BBB_GPIO23
BBB_GPIO24: U25.32(IO_L12N_3) ; port BBB_GPIO24
BBB_GPIO25: U25.30(IO_L11N_3) ; port BBB_GPIO25
BBB_GPIO26: U25.28(IO_L11P_3) ; port BBB_GPIO26
BBB_GPIO27: U25.25(IO_L09N_3) ; port BBB_GPIO27
BBB_GPIO28: U25.21(IO_L08N_3/LHCLK7) ; port BBB_GPIO28
BBB_GPIO29: U25.138(IO_L11P_0) ; port BBB_GPIO29
BBB_GPIO30: U25.120(IO_L05P_0) ; port BBB_GPIO30
BBB_GPIO31: U25.116(IO_L04N_0) ; port BBB_GPIO31
BBB_GPIO32: U25.72(IO_L14N_2/CCLK) ; port BBB_GPIO32
BBB_GPIO35: U25.79(IO_1) ; port BBB_GPIO35
BBB_GPIO36: U25.83(IO_L04P_1/RHCLK0) ; port BBB_GPIO36
BBB_GPIO37: U25.85(IO_L04N_1/RHCLK1) ; port BBB_GPIO37
BBB_GPIO38: U25.88(IO_L05N_1/TRDY1/RHCLK3) ; port BBB_GPIO38
BBB_GPIO39: U25.98(IO_L08N_1) ; port BBB_GPIO39
BBB_GPIO40: U25.101(IO_L09N_1) ; port BBB_GPIO40
BBB_GPIO42: U25.110(IO_L01P_0) ; port BBB_GPIO42
BBB_GPIO43: U25.112(IO_L02P_0/VREF_0) ; port BBB_GPIO43
BBB_GPIO44: U25.113(IO_L02N_0) ; port BBB_GPIO44
BBB_GPIO47: U25.82(IO_L03P_1) ; port BBB_GPIO47
BBB_GPIO48: U25.84(IO_L03N_1) ; port BBB_GPIO48
BBB_GPIO49: U25.87(IO_L05P_1/RHCLK2) ; port BBB_GPIO49
BBB_GPIO50: U25.96(IO_L08P_1) ; port BBB_GPIO50
BBB_GPIO52: U25.111(IO_L01N_0) ; port BBB_GPIO52
BBB_GPIO53: U25.114(IO_L04P_0) ; port BBB_GPIO53
BBB_GPIO54: U25.99(IO_L09P_1) ; port BBB_GPIO54
BBB_GPO0: U25.57(IO_L09P_2/GCLK0) ; port BBB_GPO0
BBB_GPO1: U25.59(IO_L09N_2/GCLK1) ; port BBB_GPO1
BBB_SYS_RESETN: U25.90(IO_L06P_1/RHCLK4) ; port BBB_SYS_RESETN
BCLK: R180.2 TP49.1 U25.58(IO_L10P_2/GCLK2)
CONVST: U25.91(IO_L07P_1/IRDY1/RHCLK6) ; port CONVST
CSn: U25.3(IO_L02P_3) ; port CSn
EVM2_ADC_CONVST: U25.121(IO_L05N_0) ; port EVM2_ADC_CONVST
EVM2_ADC_CSn: U25.126(IO_L06N_0/GCLK5) ; port EVM2_ADC_CSn
EVM2_ADC_RESETn: U25.125(IO_L07P_0/GCLK6) ; port EVM2_ADC_RESETn
EVM2_ADC_RVS: U25.129(IO_L08P_0/GCLK8) ; port EVM2_ADC_RVS
EVM2_ADC_SCLK: U25.127(IO_L07N_0/GCLK7) ; port EVM2_ADC_SCLK
EVM2_ADC_SDI: U25.124(IO_L06P_0/GCLK4) ; port EVM2_ADC_SDI
EVM2_ADC_SDO0: U25.130(IO_L09P_0/GCLK10) ; port EVM2_ADC_SDO0
EVM2_ADC_SDO1: U25.131(IO_L08N_0/GCLK9) ; port EVM2_ADC_SDO1
EVM2_ADC_SDO2: U25.132(IO_L09N_0/GCLK11) ; port EVM2_ADC_SDO2
EVM2_ADC_SDO3: U25.134(IO_L10P_0) ; port EVM2_ADC_SDO3
FSTS0_LED: R209.1 U25.75(IO_L02P_1/LDC1) ; port BBB_GPIO33
FSTS1_LED: R264.1 U25.76(IO_L01P_1/HDC) ; port BBB_GPIO45
FSTS2_LED: R266.1 U25.77(IO_L02N_1/LDC0) ; port BBB_GPIO34
FSTS3_LED: R265.1 U25.78(IO_L01N_1/LDC2) ; port BBB_GPIO46
NISO_SCL: U25.103(IO_L11P_1) ; port NISO_SCL
NISO_SDA: U25.104(IO_L10N_1) ; port NISO_SDA
RVS: U25.93(IO_L07N_1/RHCLK7) ; port RVS
SCLK: U25.92(IO_L06N_1/RHCLK5) ; port SCLK
SDI: U25.4(IO_L01P_3) ; port SDI
SDO0: U25.8(IO_L03N_3) ; port SDO0
SDO1: U25.5(IO_L02N_3) ; port SDO1
SDO2: U25.6(IO_L01N_3) ; port SDO2
SDO3: U25.7(IO_L03P_3) ; port SDO3
SRESETn: U25.105(IO_L11N_1) ; port SRESETn
TCK: J19.4 R197.1 R201.2
TDI: J19.2 R192.1 R202.2
TDO: J19.3 R194.1 R203.2
TMS: J19.1 R198.1 R211.2
X1_DONE: D6.2(A) R188.2 U25.73(DONE)
X1_INIT: R196.2 U25.67(IO_L12P_2/INIT_B)
X1_M0: R181.2 U25.38(IO_L01N_2/M0)
X1_M1: R182.2 U25.37(IO_L01P_2/M1)
X1_M2: R183.2 U25.39(IO_L02P_2/M2)
X1_PROG_B: R191.2 U25.144(PROG_B)
X1_SUSPEND: R184.1 R185.2 U25.74(SUSPEND)
X1_VS0: R216.2 R217.1 U25.45(IO_L04N_2/VS0)
X1_VS1: R214.2 U25.44(IO_L03N_2/VS1)
X1_VS2: R218.2 U25.43(IO_L04P_2/VS2)
NetD6_1: D6.1(K) R187.2
NetD22_1: D22.1(K) R209.2
NetD23_1: D23.1(K) R264.2
NetD24_1: D24.1(K) R265.2
NetD25_1: D25.1(K) R266.2
NetR179_1: R179.1 Y2.1(E/D)
NetR180_1: R180.1 Y2.3(OUT)
NetR192_2: R192.2 U25.2(TDI)
NetR194_2: R194.2 U25.107(TDO)
NetR197_2: R197.2 U25.109(TCK)
NetR198_2: R198.2 U25.1(TMS)
NetTP33_1: TP33.1 U25.141(IO_L12P_0/VREF_0)
NetTP34_1: TP34.1 U25.143(IO_L12N_0/PUDC_B)

Not connected (* = marked no-connect by the designer): U25 33(IP_L13P_3) 35(IP_L13N_3/VREF_3) 41(IO_L02N_2/CSO_B) 42(IO_L03P_2/RDWR_B) 53(IP_2/VREF_2) 62(IO_2/MOSI/CSI_B) 80(IP_1/VREF_1) 97(IP_1/VREF_1) 123(IP_0/VREF_0)

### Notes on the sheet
- 1P8V IO
- 3P3VI O
- Text String
- VCCAUX
- VCCINT
- (near R184) DNP
- VCCO_0
- VCCO_1
- VCCO_2
- VCCO_3
- DNP
- 33 MHz READ CLOCK

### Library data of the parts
C86 = GRM155R71C104KA88D: as C51 on sheet TIDA-00732_ADC
C156-C159 C166-C169 C176-C183 C198-C205 = C1005X7R1H102M: as C92 on sheet TIDA-00732_FPGA_1
C160 C161 C170 C171 C184-C187 C206-C209 = ZRB18AD71A106KE01L: as C219 on sheet TIDA-00732_ADC
C162-C165 C172-C175 C188-C191 C193-C196 C210-C213 C215-C218 = GRM155R61A473KA01D: as C98 on sheet TIDA-00732_FPGA_1
D6 D22-D25 = 150060RS75000: as D5 on sheet TIDA-00732_FPGA_1
J19 = PEC06SAAN: as J14 on sheet TIDA-00732_FPGA_1
R179 R180 = CRCW040233R0JNED: as R161 on sheet TIDA-00732_FPGA_1
R181-R185 R187 R188 R191 R196 R201-R203 R211 R214 R216-R218 = RC0603FR-071KL: as R107 on sheet TIDA-00732_FPGA_1
R192 R194 R197 R198 = RG1608P-101-B-T5: as R96 on sheet TIDA-00732_ADC
R209 R264-R266 = RC0603JR-07330RL: as R227 on sheet TIDA-00732_FPGA_1
TP33 TP34 TP49 = TP-025-SMT: as TP48 on sheet TIDA-00732_FPGA_1
U25 = XC3S50AN-4TQ144C: as U24 on sheet TIDA-00732_FPGA_1
Y2 = AU-40.000MDE-T: as Y1 on sheet TIDA-00732_FPGA_1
